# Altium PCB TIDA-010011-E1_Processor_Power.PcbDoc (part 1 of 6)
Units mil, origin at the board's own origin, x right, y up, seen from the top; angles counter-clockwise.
Board outline 4921.26 x 4921.26 mil, 4 copper layers (Top Layer, Gnd layer, Gnd/Pwr layer, Bottom Layer), stack 62.634 mil thick; 631 components, 254 nets, 1751 pads, 757 vias.
Unrouted connection lines stored in the file: 1.
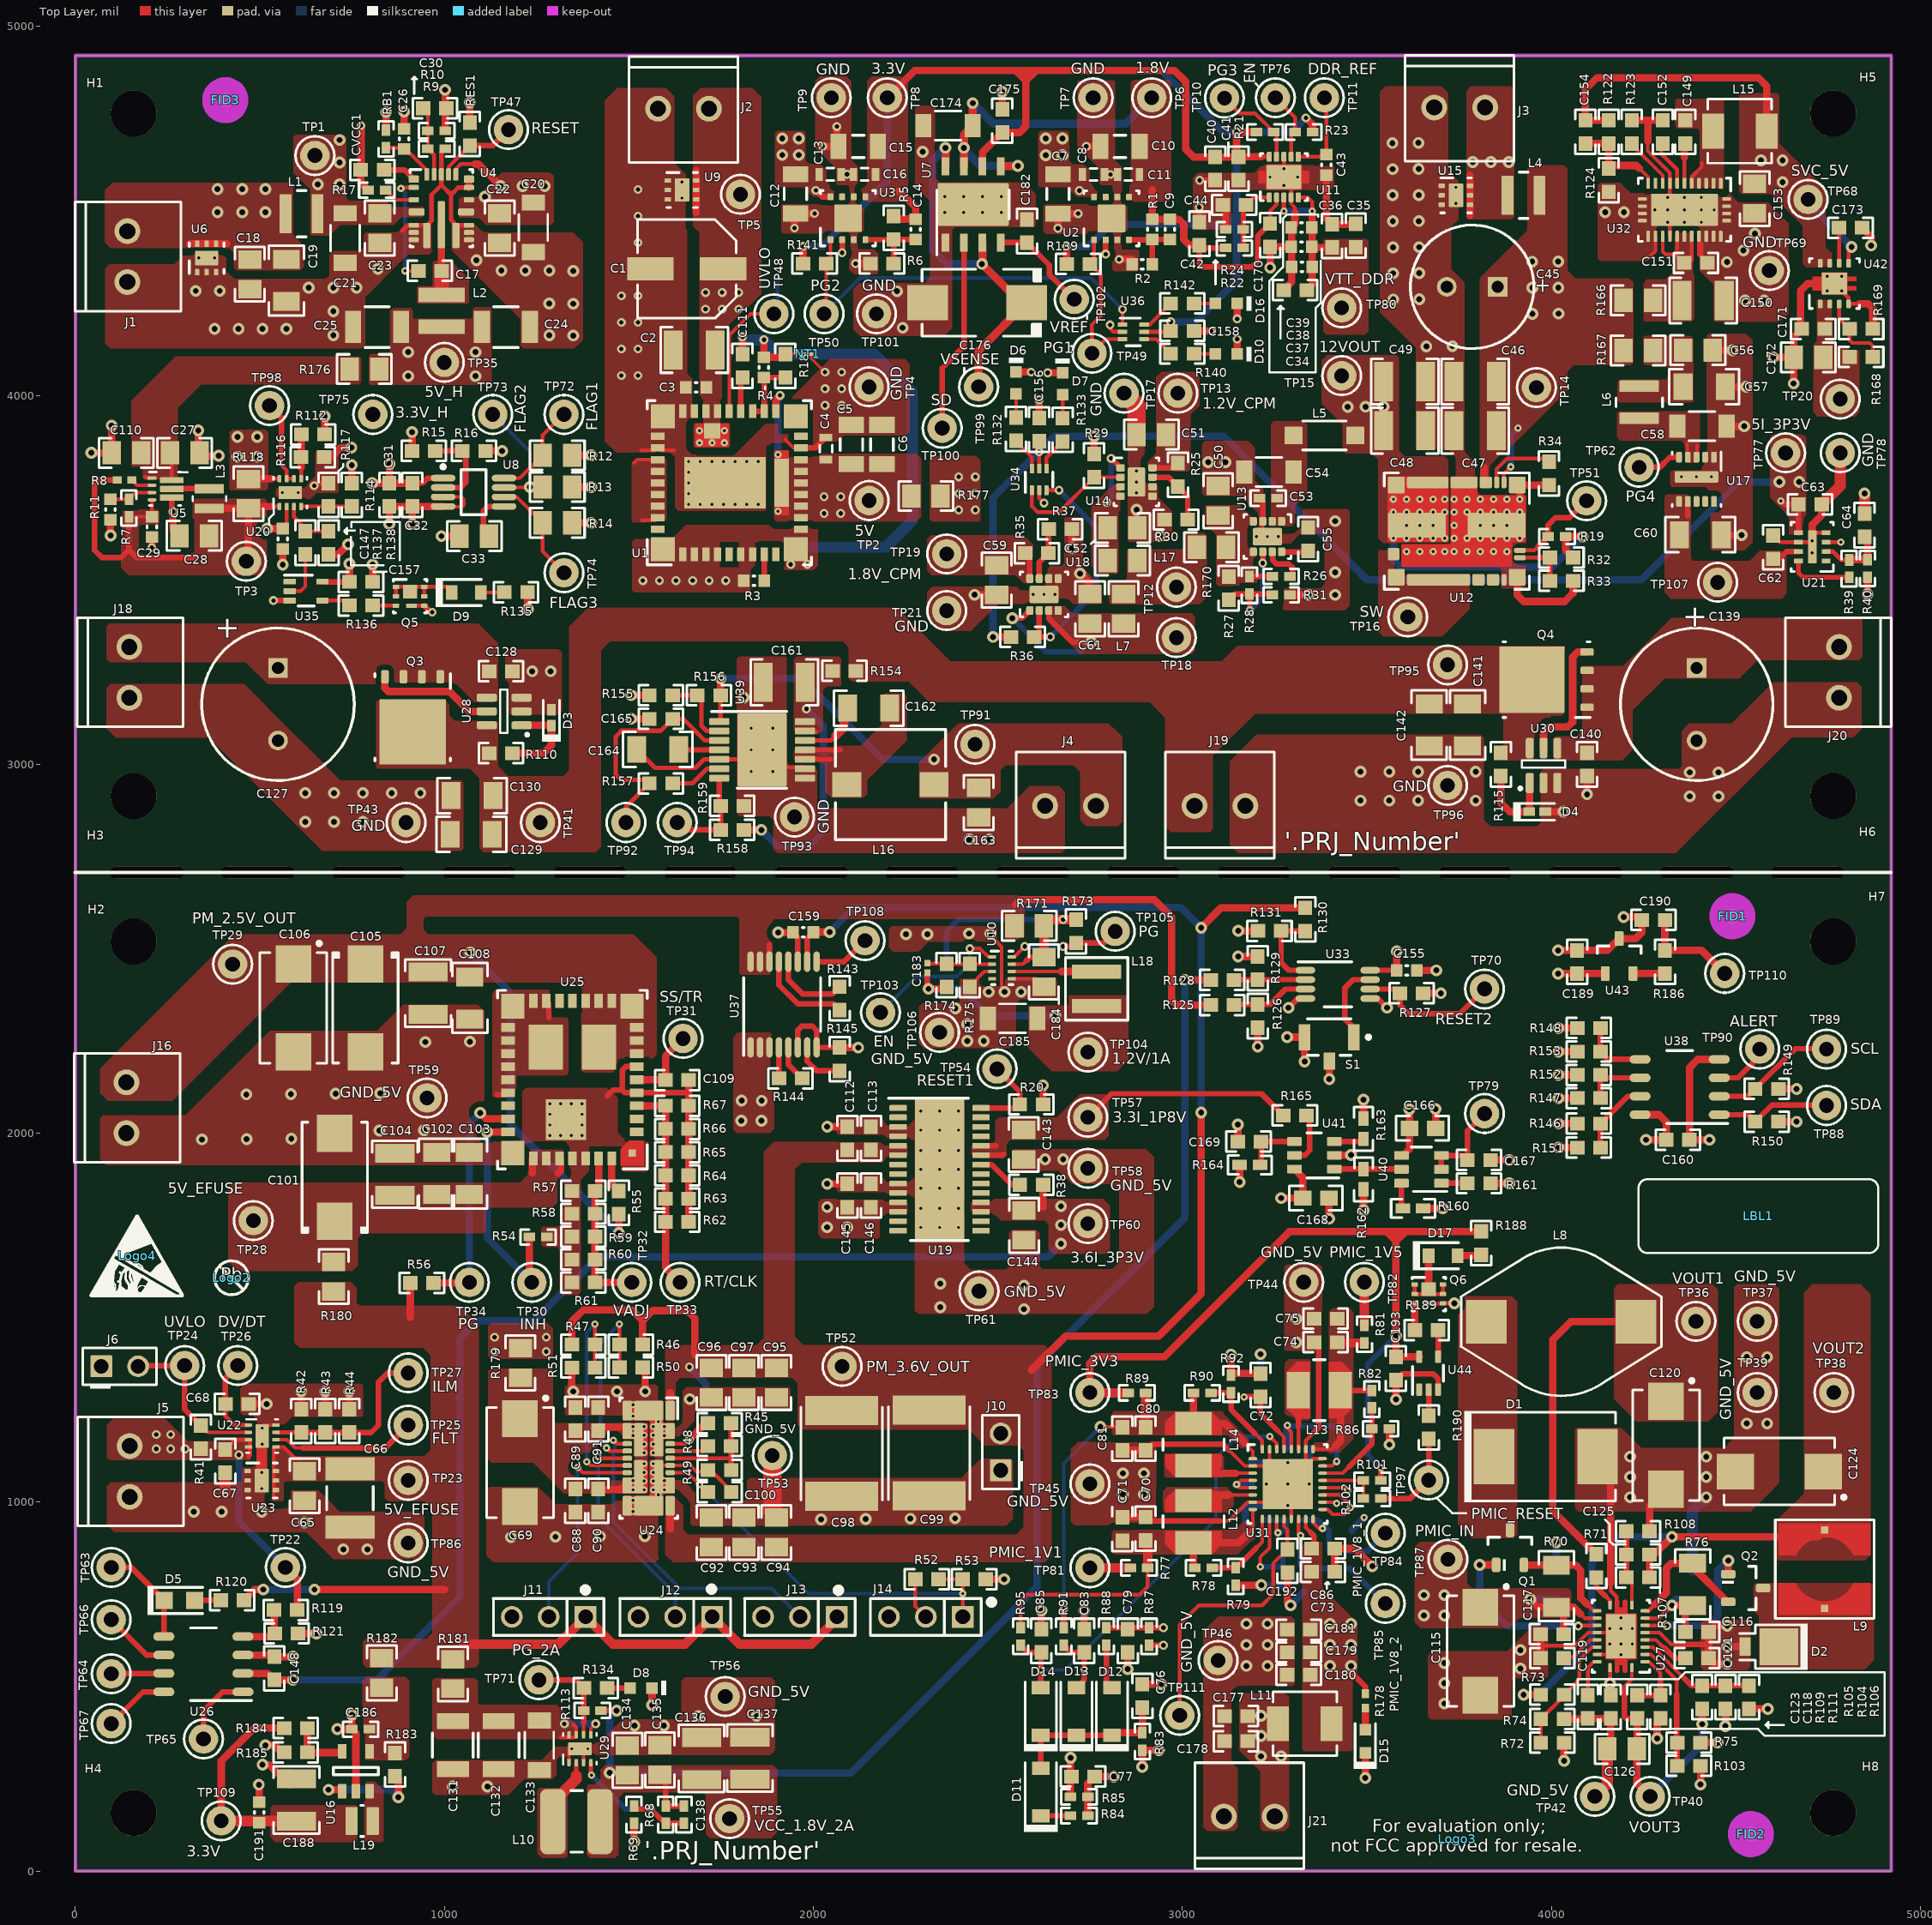
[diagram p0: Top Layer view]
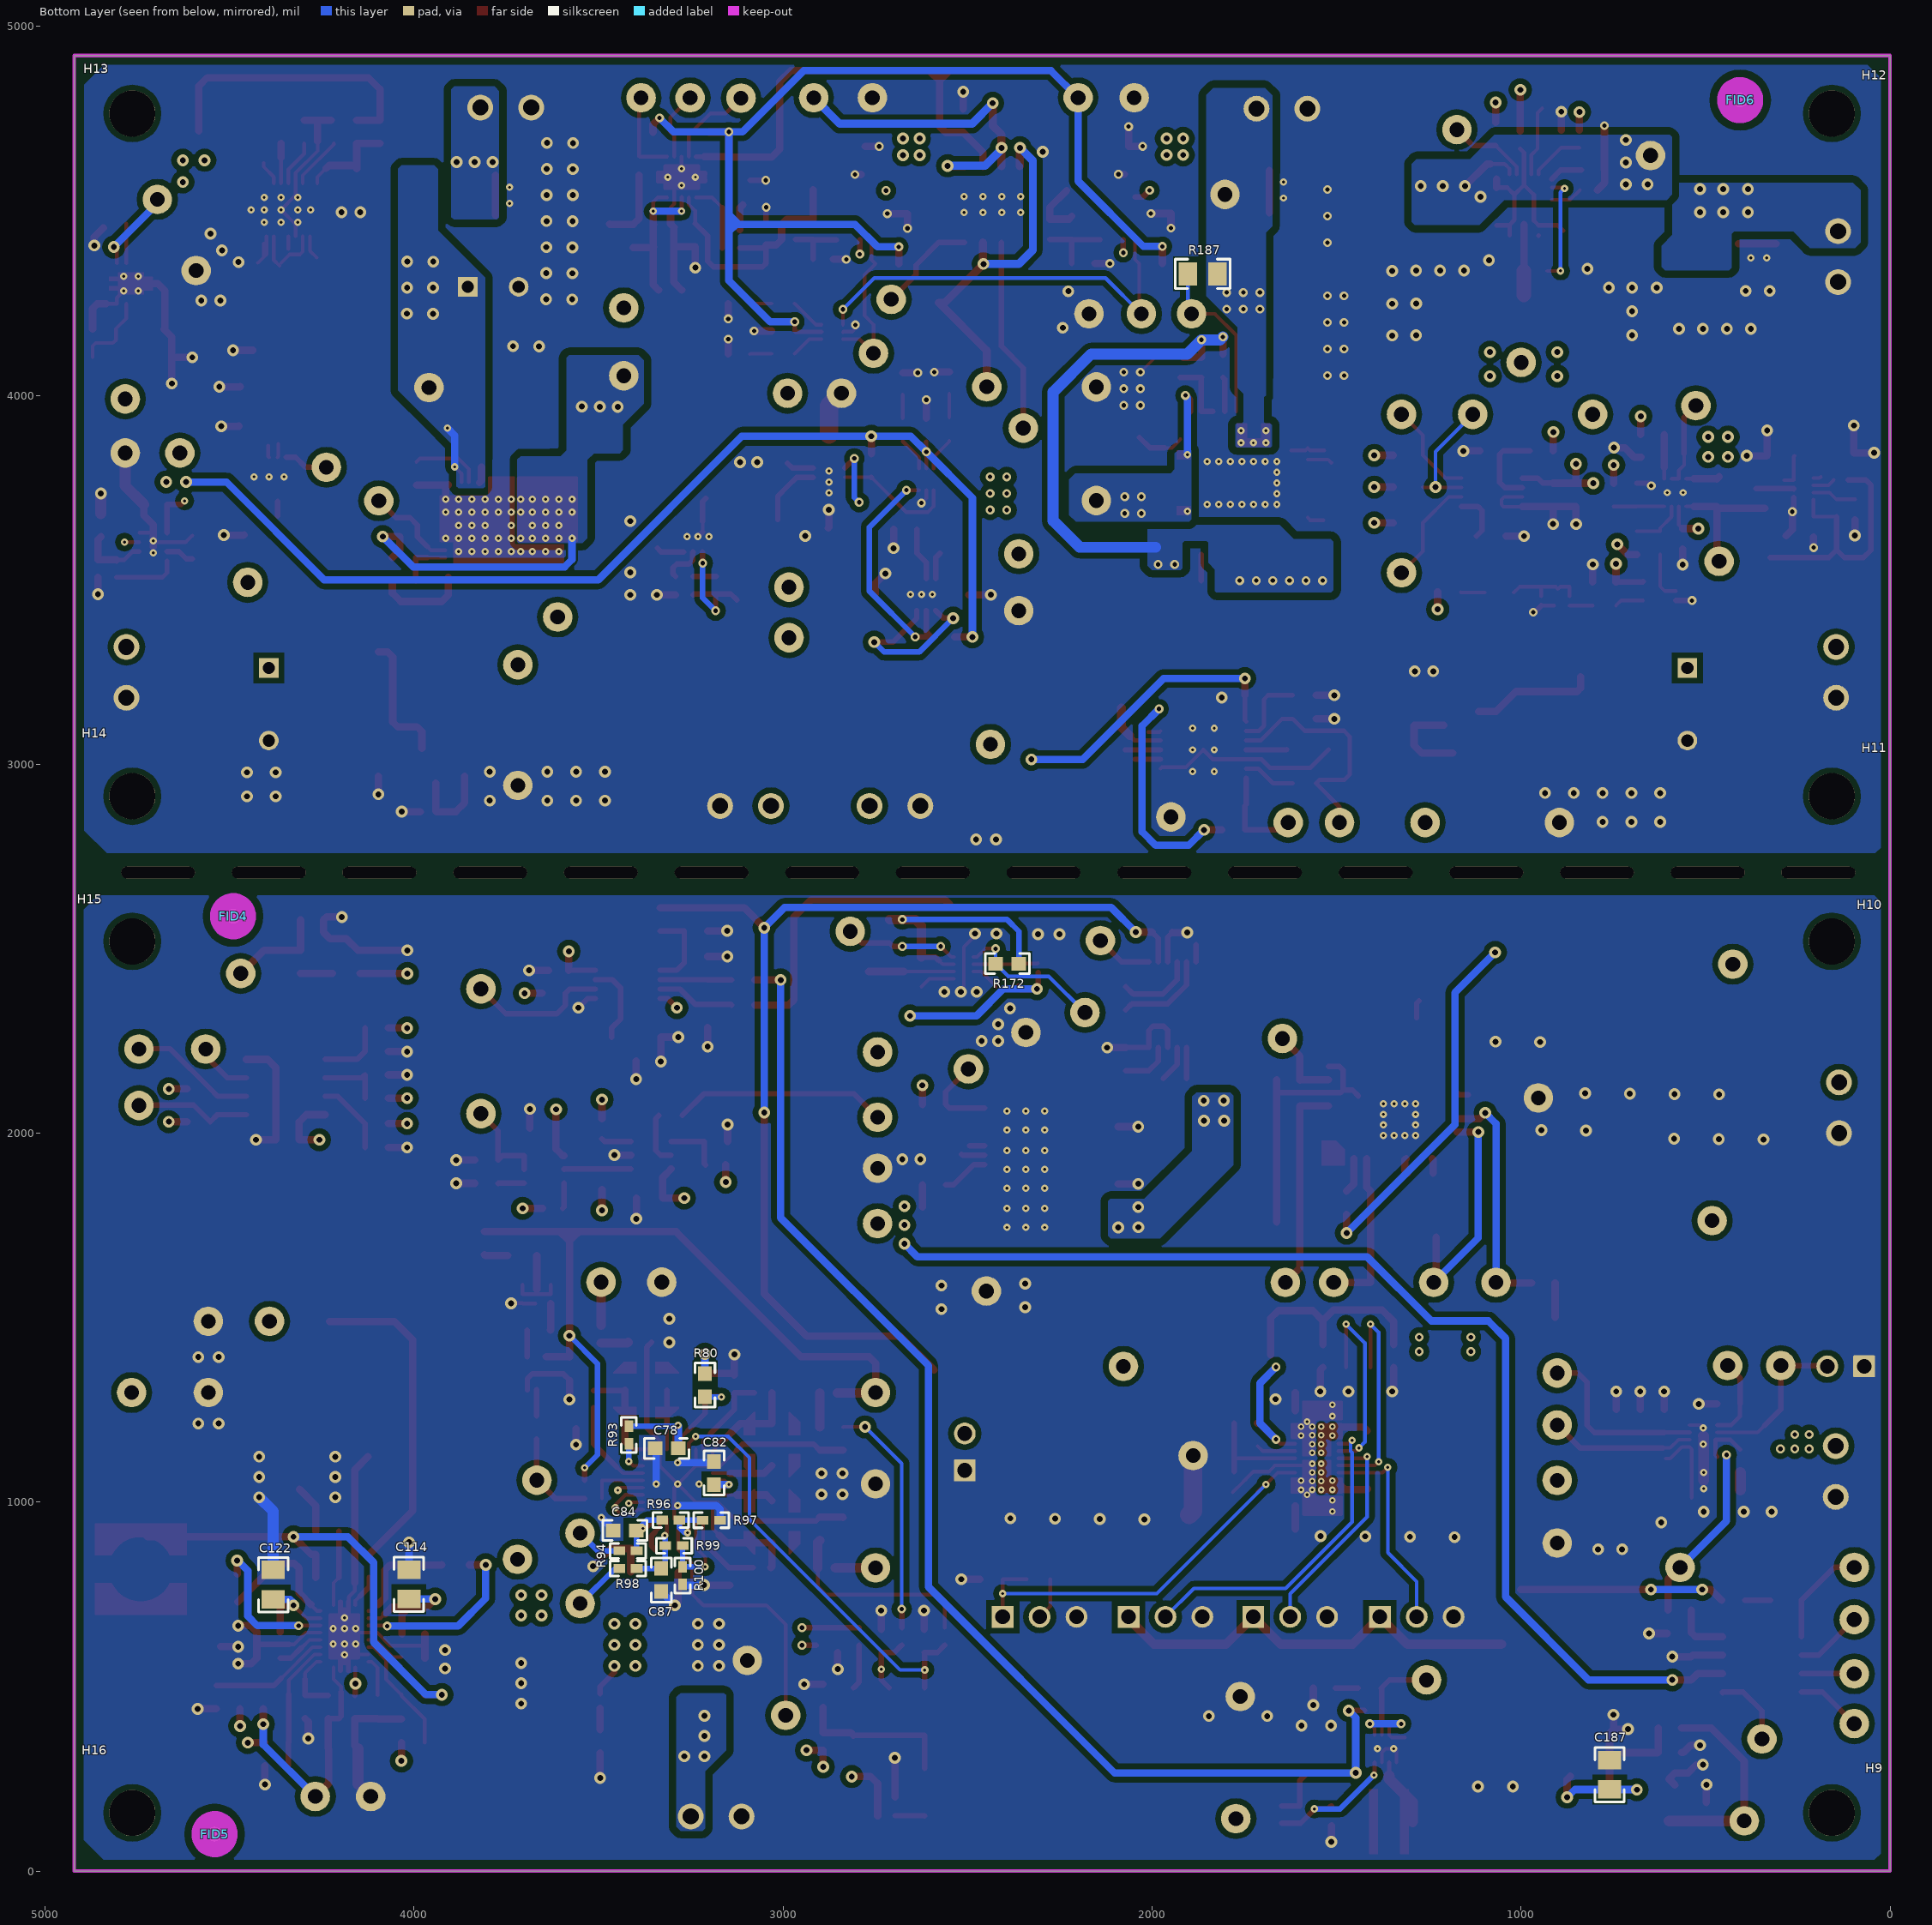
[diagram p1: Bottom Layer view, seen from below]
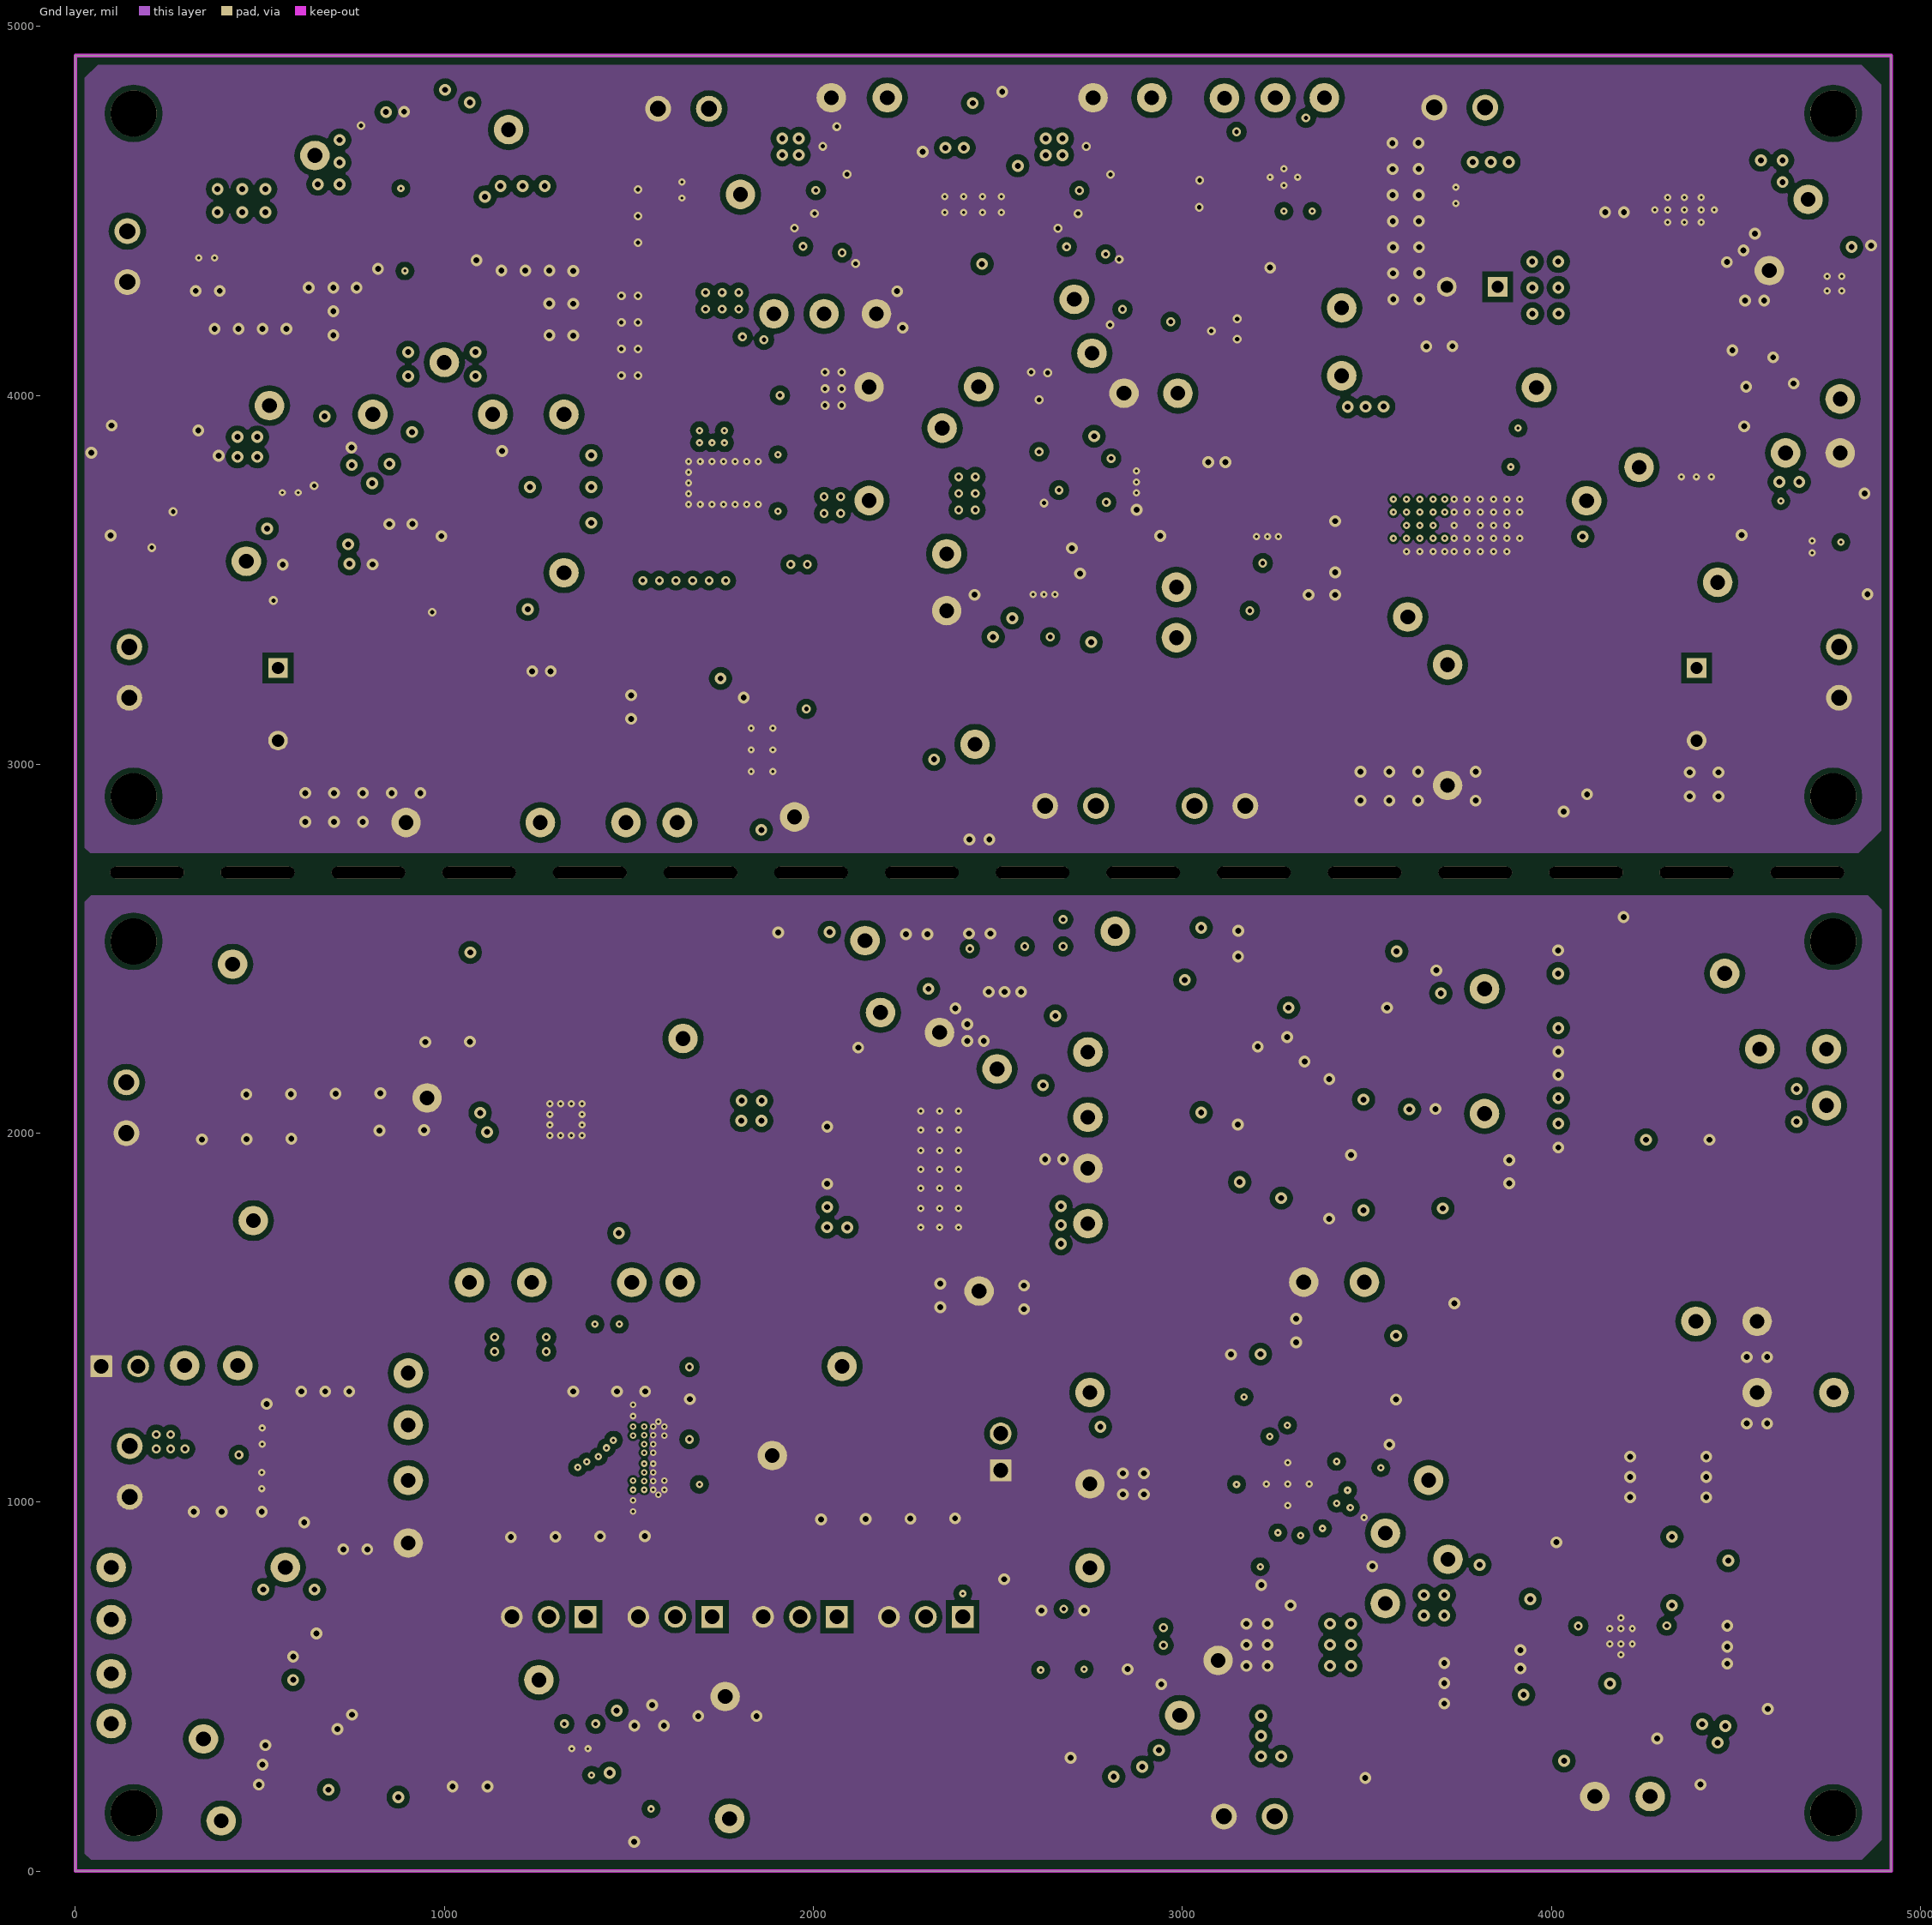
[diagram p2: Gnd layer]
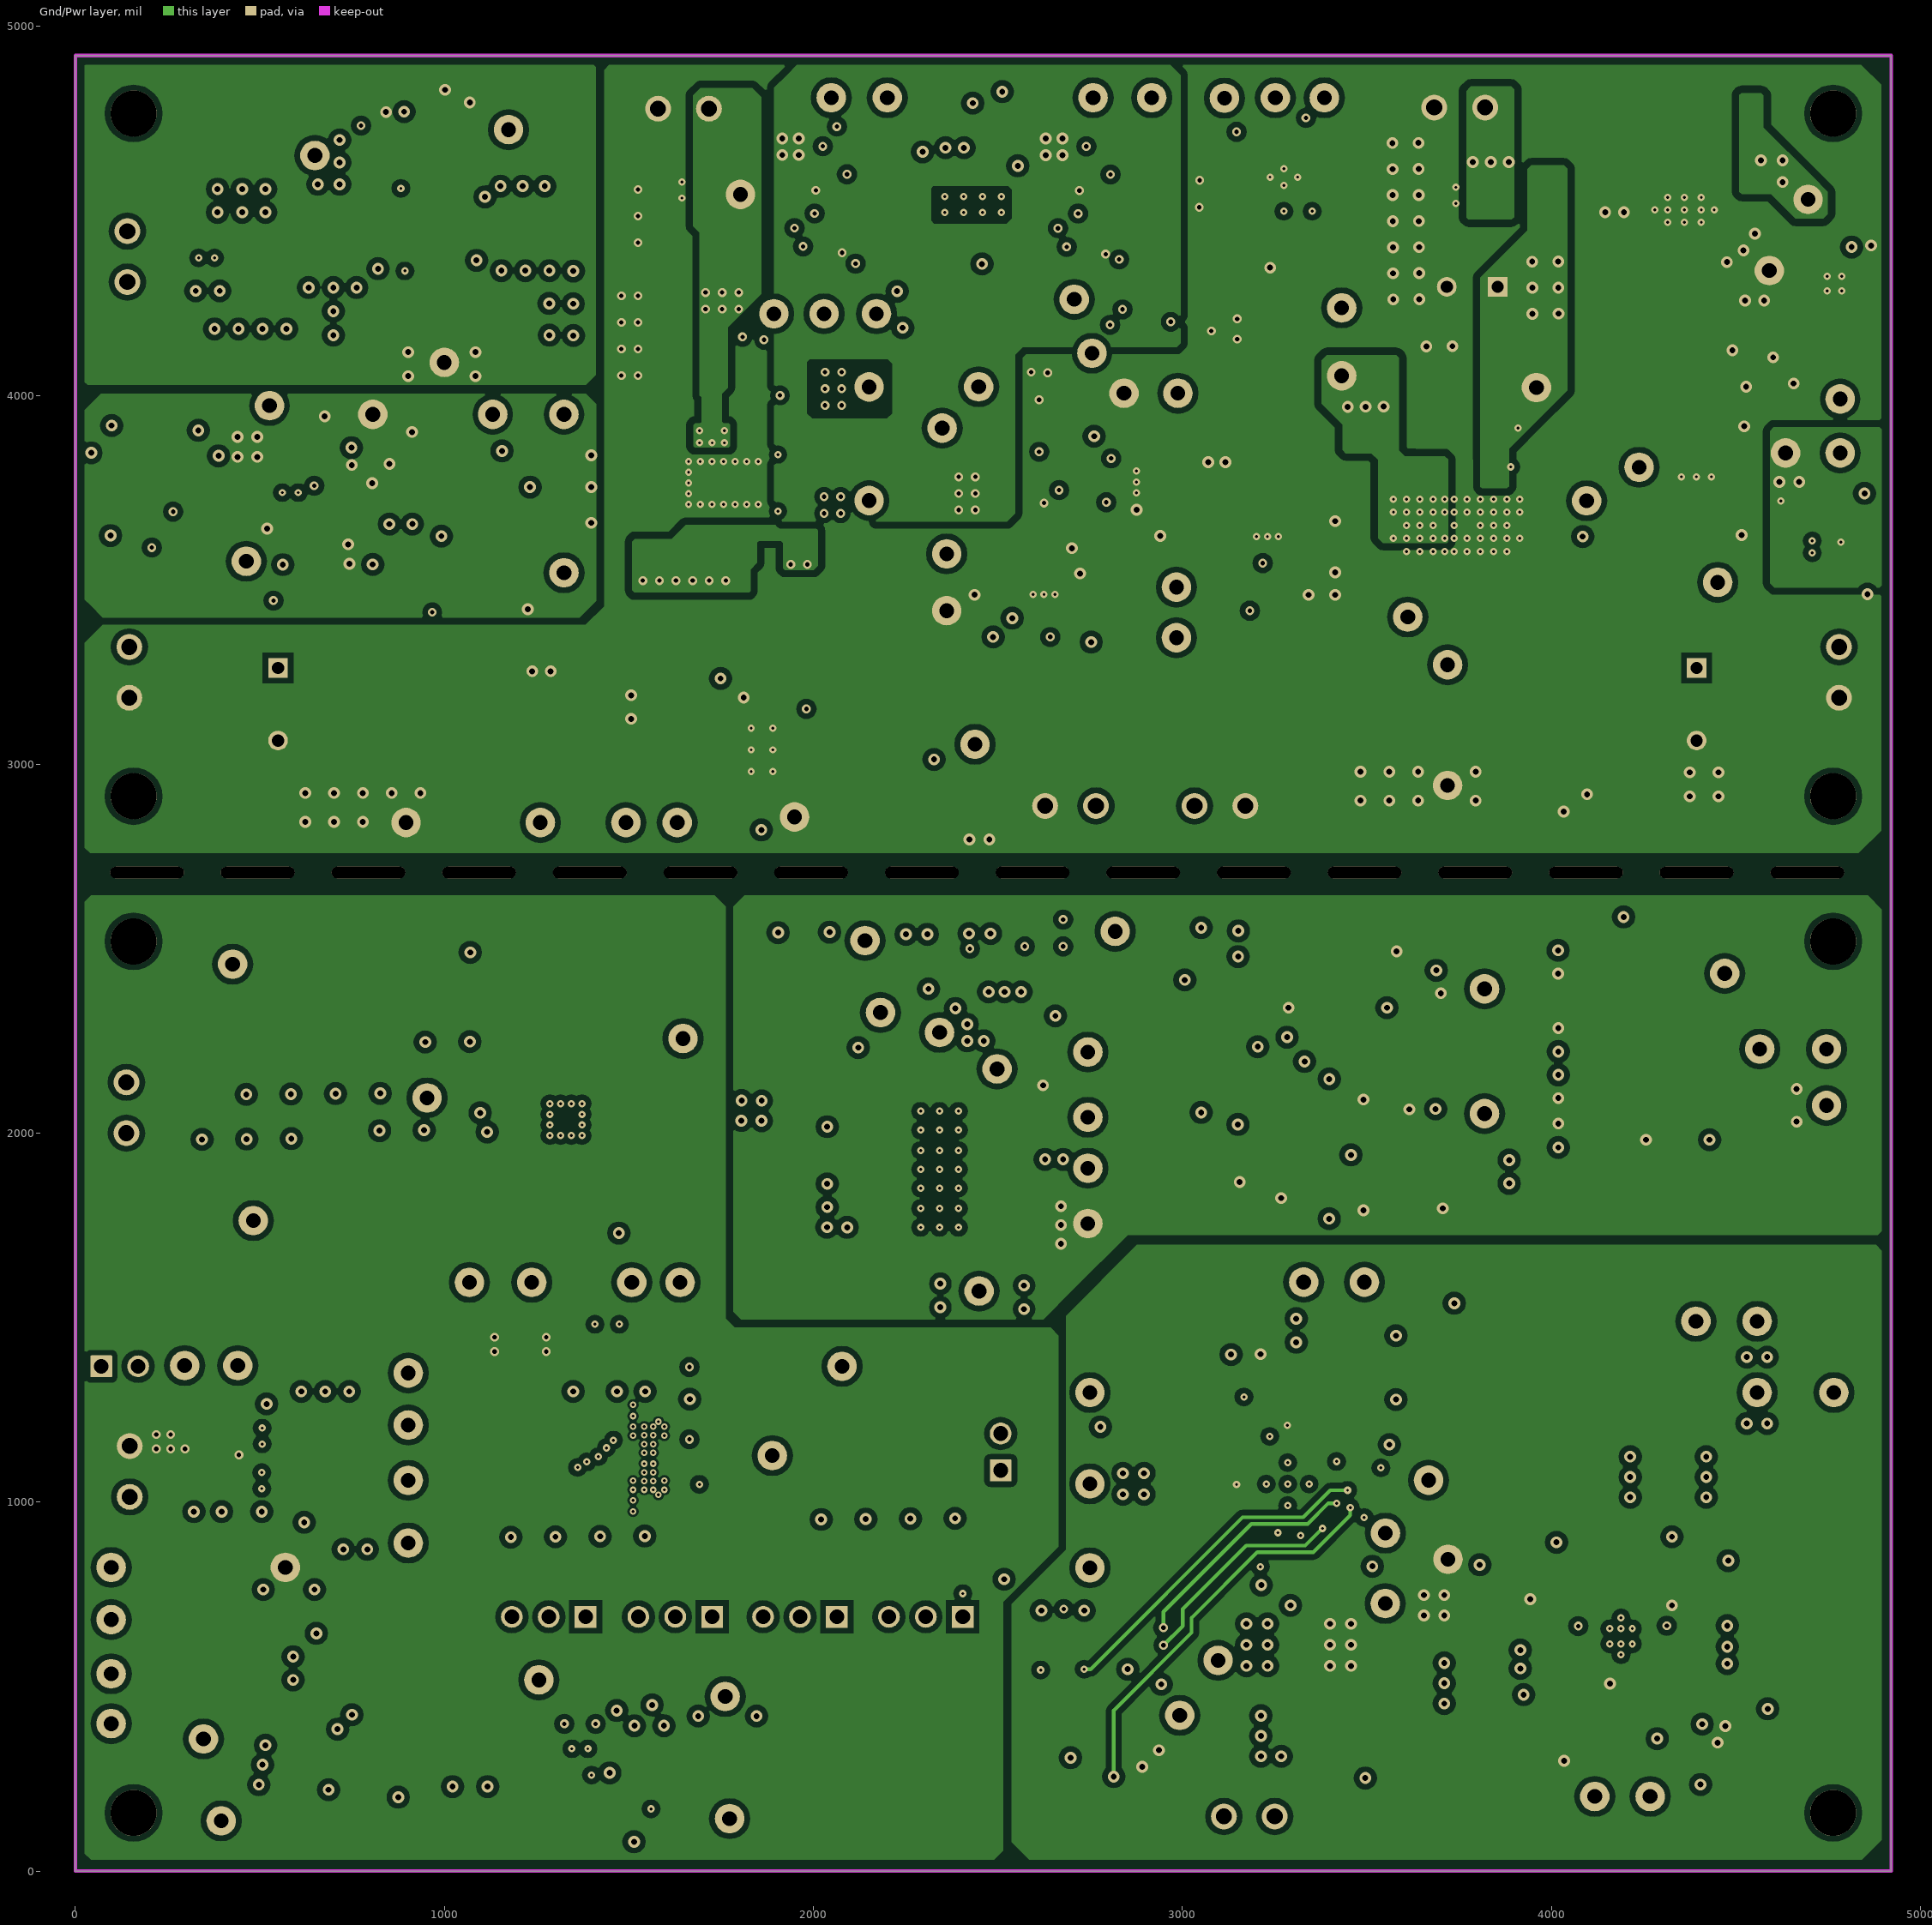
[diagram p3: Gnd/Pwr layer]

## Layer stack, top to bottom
Top Solder: solder mask 0.3, Solder Resist, Dk 3.5
Top Layer: signal copper 1.4
Dielectric1: core 16, FR-4 High Tg, Dk 4.2
Gnd layer: signal copper 1.417
Dielectric 2: prepreg 25, FR-4 High Tg, Dk 4.5
Gnd/Pwr layer: signal copper 1.417
Dielectric 3: core 16, FR-4 High Tg, Dk 4.2
Bottom Layer: signal copper 1.4
Bottom Solder: solder mask 0.3, Solder Resist, Dk 3.5

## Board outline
0,0 0,4921.26 4921.26,4921.26 4921.26,0

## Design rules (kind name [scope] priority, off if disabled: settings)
AcuteAngle [All] p1: minimum=4.50000000000000E+0001 checktracksonly=FALSE
AssemblyTestPointUsage [All] p1: valid=2
BoardOutlineClearance BoardOutlineClearance_MountingHoles [OnCopper and InComponentClass('Mounting Holes')] p1: gap=30 ignorepadtopadclearanceinfootprint=FALSE
BoardOutlineClearance BoardOutlineClearance_Poly [OnCopper and InPoly] p2: gap=25 ignorepadtopadclearanceinfootprint=FALSE
BoardOutlineClearance [OnCopper and Not InComponentClass('Logo') and not InComponentClass('FiducialMark') and not InRegion(1000,500,4000,800)] p3: gap=15 ignorepadtopadclearanceinfootprint=FALSE
Clearance Clearance_room_1 [WithinRoom('TIDA-010011-E1_Processor_Power _Pg8')] p1: gap=5.9 ignorepadtopadclearanceinfootprint=FALSE except(0: Arc-Hole Track-Hole SMDPad-Hole THPad-Hole Via-Hole Fill-Hole Poly-Hole Region-Hole Text-Hole)
Clearance Clearance_room1 [WithinRoom('RoomDefinition')] p2: gap=5.9 ignorepadtopadclearanceinfootprint=FALSE except(0: Arc-Hole Track-Hole SMDPad-Hole THPad-Hole Via-Hole Fill-Hole Poly-Hole Region-Hole Text-Hole)
Clearance Clearance_u4 [InPadClass('u4')] p3: gap=5.9 ignorepadtopadclearanceinfootprint=FALSE except(0: Arc-Hole Track-Hole SMDPad-Hole THPad-Hole Via-Hole Fill-Hole Poly-Hole Region-Hole Text-Hole)
Clearance Clearance_U11 [InPadClass('U11')] p4: gap=5.9 ignorepadtopadclearanceinfootprint=FALSE except(0: Arc-Hole Track-Hole SMDPad-Hole THPad-Hole Via-Hole Fill-Hole Poly-Hole Region-Hole Text-Hole)
Clearance Clearance_Poly_poly [InPoly vs InPoly] p5: gap=20 ignorepadtopadclearanceinfootprint=FALSE except(0: Arc-Hole Track-Hole SMDPad-Hole THPad-Hole Via-Hole Fill-Hole Poly-Hole Region-Hole Text-Hole)
Clearance Clearance_Keepouts [IsKeepOut vs InPolygon] p6: gap=20 ignorepadtopadclearanceinfootprint=FALSE except(0: Arc-Hole Track-Hole SMDPad-Hole THPad-Hole Via-Hole Fill-Hole Poly-Hole Region-Hole Text-Hole)
Clearance Clearance_Poly [InPolygon] p7: gap=15 ignorepadtopadclearanceinfootprint=FALSE except(0: Arc-Hole Track-Hole SMDPad-Hole THPad-Hole Via-Hole Fill-Hole Poly-Hole Region-Hole Text-Hole)
Clearance [All] p8: gap=7.7 ignorepadtopadclearanceinfootprint=FALSE except(0: Arc-Hole Track-Hole SMDPad-Hole THPad-Hole Via-Hole Fill-Hole Poly-Hole Region-Hole Text-Hole)
ComponentClearance ComponentClearance_MountingHoles_FiducialMarks [InComponentClass('Mounting Holes') vs InComponentClass('FiducialMark')] p1: gap=10 collisioncheckmode=3 verticalgap=10 showdistances=FALSE
ComponentClearance ComponentClearance_Shunt [InComponentClass('Header') vs InComponentClass('Shunt')] p2: gap=0 collisioncheckmode=3 verticalgap=0 showdistances=FALSE
ComponentClearance ComponentClearance_Logo [InComponentClass('Logo')] p3: gap=5 collisioncheckmode=3 verticalgap=5 showdistances=FALSE
ComponentClearance ComponentClearance_ScrewToNut [(HasFootprint('NY PMS 440 0025 PH')) vs (HasFootprint('Keystone_1902C'))] p4: gap=5 collisioncheckmode=3 verticalgap=10 showdistances=FALSE
ComponentClearance ComponentClearance_MountingHoles [InComponentClass('Mounting Holes')] p5: gap=250 collisioncheckmode=3 verticalgap=100000 showdistances=FALSE
ComponentClearance ComponentClearance_SmallPassives [HasFootprint('0201*') or HasFootprint('0402*') or HasFootprint('0508') or HasFootprint('0603*') or HasFootprint('0612') or HasFootprint('0805*') or HasFootprint('0815*') or HasFootprint('0830*') or HasFootprint('1206*') or HasFootprint('1210*') or HasFootprint('1808*') or HasFootprint('1812*') or HasFootprint('1825*') or HasFootprint('2010*') or HasFootprint('2220*') or HasFootprint('2225*') or HasFootprint('2512*') or HasFootprint('2728*') or HasFootprint('3518*') vs HasFootprint('0201*') or HasFootprint('0402*') or HasFootprint('0508') or HasFootprint('0603*') or HasFootprint('0612') or HasFootprint('0805*') or HasFootprint('0815*') or HasFootprint('0830*') or HasFootprint('1206*') or HasFootprint('1210*') or HasFootprint('1808*') or HasFootprint('1812*') or HasFootprint('1825*') or HasFootprint('2010*') or HasFootprint('2220*') or HasFootprint('2225*') or HasFootprint('2512*') or HasFootprint('2728*') or HasFootprint('3518*')] p6: gap=5 collisioncheckmode=3 verticalgap=5 showdistances=FALSE
ComponentClearance ComponentClearance_THtoSMT [IsThruComponent vs IsSMTComponent] p7: gap=5 collisioncheckmode=3 verticalgap=5 showdistances=FALSE
ComponentClearance ComponentClearance_THtoTH [IsThruComponent vs IsThruComponent] p8: gap=0 collisioncheckmode=3 verticalgap=10 showdistances=FALSE
ComponentClearance [All] p9: gap=10 collisioncheckmode=3 verticalgap=10 showdistances=FALSE
DiffPairsRouting [All] p1: maxlimit=100 minlimit=10 mostfreqgap=10 toplayer_minwidth=15 toplayer_maxwidth=15 toplayer_prefwidth=15 midlayer1_minwidth=15 midlayer1_maxwidth=15 midlayer1_prefwidth=15 midlayer2_minwidth=15 midlayer2_maxwidth=15 midlayer2_prefwidth=15 bottomlayer_minwidth=15 bottomlayer_maxwidth=15 bottomlayer_prefwidth=15 maxuncoupledlength=1000
FabricationTestPointUsage TestPointUsage [All] p1: valid=2 allowmultiple=FALSE
FabricationTestpoint Testpoint [All] p1: side=3 testpointundercomponent=TRUE minsize=40 maxsize=100 preferedsize=60 minholesize=0 maxholesize=40 preferedholesize=32 testpointgrid=1 allowsidetop=TRUE allowsidebottom=TRUE usegrid=TRUE gridtolerance=0.01
FanoutControl Fanout_LCC [IsLCC] p1: bgadir=Out bgaviamode=Centered fanoutstyle=Auto fanoutdirection=Alternating viagrid=1 // Fanout_LCC (Default Rule)
FanoutControl Fanout_BGA [IsBGA] p2: bgadir=Out bgaviamode=Centered fanoutstyle=Auto fanoutdirection=Alternating viagrid=1 // Fanout_BGA (Default Rule)
FanoutControl Fanout_Default [All] p4: bgadir=Out bgaviamode=Centered fanoutstyle=Auto fanoutdirection=Alternating viagrid=1 // Fanout_Default (Default Rule)
FanoutControl Fanout_Small [(CompPinCount < 5)] p5: bgadir=Out bgaviamode=Centered fanoutstyle=Auto fanoutdirection=OutThenIn viagrid=1 // Fanout_Small (Default Rule)
Height [All] p1: minheight=0 maxheight=99999 prefheight=500
HoleSize [All] p1: absolutevalues=TRUE maxlimit=251 minlimit=7.87 maxpercent=80.000 minpercent=20.000
MinimumAnnularRing [All] p1: minimumring=4
MinimumSolderMaskSliver MinimumSolderMaskSliver_Logo [InComponentClass('Logo') vs InComponentClass('Logo')] p1: minsoldermaskwidth=0.7
MinimumSolderMaskSliver [All] p2: minsoldermaskwidth=3.94
PlaneClearance [All] p1: clearance=10
PlaneConnect [All] p1: planeconnectstyle=Relief reliefexpansion=10 reliefentries=4 reliefconductorwidth=10 reliefairgap=10
PolygonConnect PolygonConnectThermalVia [isvia] p1: connectstyle=Direct reliefconductorwidth=10 reliefentries=4 polygonreliefangle="90 Angle" airgapwidth=10
PolygonConnect PolygonConnectThermalPad [((ObjectKind = 'Pad') And (((Name Like 'U*') or (Name Like 'D*')) and (InComponentClass('TIDA-00183_pg-4_Driver') or InComponentClass('TIDA-00183_pg-5_OP_Connector')))) or ((ObjectKind = 'Pad') And (Name like 'U61*'))] p2: connectstyle=Direct reliefconductorwidth=10 reliefentries=4 polygonreliefangle="90 Angle" airgapwidth=10
PolygonConnect [All] p3: connectstyle=Direct reliefconductorwidth=10 reliefentries=4 polygonreliefangle="90 Angle" airgapwidth=5
RoomDefinition "TIDA-010011-E1_Processor_Power _Pg8" [InComponentClass('TIDA-010011-E1_Processor_Power _Pg8')] p1: confinementstyle=ConfineOut formatcopy=TRUE lockcomponents=FALSE outline 1474.99,1282.31 1632.47,1282.31 1632.47,955.54 1474.99,955.54
RoomDefinition [u12] p2: confinementstyle=ConfineOut formatcopy=TRUE lockcomponents=FALSE outline 3546.85,3789.57 3940.56,3789.57 3940.56,3474.61 3546.85,3474.61
RoutingVias ThermalPadVias [IsVia and InAnyComponent] p1: holewidth=7.87 width=19.68 viastyle="Through Hole" minholewidth=7.87 minwidth=17.72 maxholewidth=12.99 maxwidth=23.62
RoutingVias [All] p2: holewidth=12 width=24 viastyle="Through Hole" minholewidth=8 minwidth=20 maxholewidth=16 maxwidth=32
SilkToBoardRegionClearance [Not ((IsComment or IsDesignator) And (Hide <> 'False')) and not InRegion(1000,500,4000,800)] p1:
SilkToSilkClearance SilkToSilkClearance_Pb-FreeLogo [(HasFootprint('Pb-Free_Overlay_Medium') OR HasFootprint('Pb-Free_Overlay_Small')) vs (HasFootprint('Pb-Free_Overlay_Medium') OR HasFootprint('Pb-Free_Overlay_Small'))] p1: silktosilkclearance=0
SilkToSilkClearance [All] p2: silktosilkclearance=4
SilkToSolderMaskClearance SilkToComponentPadClearance [IsPad and InAnycomponent] p1: minsilkscreentomaskgap=5 clearancetoexposedcopper=TRUE
SilkToSolderMaskClearance "Silk to Solder Mask Opening" [All] p2: minsilkscreentomaskgap=4 clearancetoexposedcopper=FALSE
SolderMaskExpansion [All] p1: expansion=1.97
Width [All] p1: maxlimit=100 minlimit=6 preferedwidth=10 checkconnectedcopper=TRUE
13 further rules are at their usual default settings.

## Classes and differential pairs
component class "TIDA-010011-E1_Processor_Power _Pg9": C131 C132 C133 C134 C135 C136 C137 C138 C183 C184 C185 C186 C187 C188 C191 D8 L10 L18 L19 R68 R69 R113 R134 R171 R172 R173 R174 R175 R181 R182 R183 R184 R185 TP55 TP56 TP71 TP103 TP104 TP105 TP106 TP109 U10 U16 U29
pad class U11: U8-1 U8-2 U8-3 U8-4 U8-5 U8-6 U8-7 U8-8 U11-1 U11-2 U11-3 U11-4 U11-5 U11-6 U11-7 U11-8 U11-9 U11-10 U11-11 U12- U12-1 U12-2 U12-3 U12-4 U12-5 U12-6 U12-7 U12-8 U12-9 U12-10 U12-11 U12-12 U12-13 U12-14 U12-15 U12-16 U12-17 U12-18 U13-0 U13-1 U13-2 U13-3 U13-4 U13-5 U13-6 U13-7 U13-8 U13-9 U14-1 U14-2 U14-3 U14-4 U14-5 U14-6 U14-7 U14-8 U14-9 U18-1 U18-2 U18-3 U18-4 U18-5 U18-6 U18-7 U18-8 U18-9 U24-1 U24-2 U24-3 U24-4 U24-5 U24-6 U24-7 U24-8 U24-9 U24-10 U24-11 U24-12 U24-13 U24-14 U24-15 U24-16 U24-17 U24-18 U24-19 U24-20 U24-21 U24-22 U24-23 U24-24
component class "TIDA-010011-E1_Processor_Power _Pg3": C17 C18 C19 C20 C21 C22 C23 C24 C25 C26 C27 C28 C29 C30 C31 C32 C33 C110 C147 C157 CVCC1 D9 J1 L1 L2 L3 Q5 R7 R8 R9 R10 R11 R12 R13 R14 R15 R16 R17 R112 R114 R116 R117 R118 R135 R136 R137 R138 R176 RB1 RES1 TP1 TP3 TP35 TP47 TP72 TP73 TP74 TP75 TP98 U4 U5 U6 U8 U20 U35
component class "TIDA-010011-E1_Processor_Power _Pg4": C1 C2 C3 C4 C5 C6 C7 C8 C9 C10 C11 C12 C13 C14 C15 C16 C34 C35 C36 C37 C38 C39 C40 C41 C42 C43 C44 C111 C158 C170 C174 C175 C176 C182 D10 D16 J2 NT1 R1 R2 R3 R4 R5 R6 R18 R21 R22 R23 R24 R139 R140 R141 R142 R177 R187 TP2 TP4 TP5 TP6 TP7 TP8 TP9 TP10 TP11 TP48 TP49 TP50 TP76 TP80 TP99 TP100 TP101 TP102 U1 U2 U3 U7 U9 U11 U36
component class "TIDA-010011-E1_Processor_Power _EVM_Hardware_Pg11": FID1 FID2 FID3 FID4 FID5 FID6 H1 H2 H3 H4 H5 H6 H7 H8 H9 H10 H11 H12 H13 H14 H15 H16 LBL1 Logo2 Logo3 Logo4 ZZ1 ZZ2 ZZ3 ZZ4
component class FiducialMark: FID1 FID2 FID3 FID4 FID5 FID6
component class AssemblyNote: ZZ1 ZZ2 ZZ3 ZZ4
component class Header: J6 J10 J11 J12 J13 J14
component class "TIDA-010011-E1_Processor_Power _Pg5": C45 C46 C47 C48 C49 C50 C51 C52 C53 C54 C55 C56 C57 C58 C59 C60 C61 C62 C63 C64 C156 D6 D7 J3 L4 L5 L6 L7 L17 R19 R25 R26 R27 R28 R29 R30 R31 R32 R33 R34 R35 R36 R37 R39 R40 R132 R133 R167 R170 TP12 TP13 TP14 TP15 TP16 TP17 TP18 TP19 TP21 TP51 TP62 TP77 TP78 TP107 U12 U13 U14 U15 U17 U18 U21 U34
component class "TIDA-010011-E1_Processor_Power _Pg7": C65 C66 C67 C68 C69 C88 C89 C90 C91 C92 C93 C94 C95 C96 C97 C98 C99 C100 C148 D5 J5 J6 J10 J11 J12 J13 J14 R41 R42 R43 R44 R45 R46 R47 R48 R49 R50 R51 R52 R53 R119 R120 R121 R179 TP22 TP23 TP24 TP25 TP26 TP27 TP52 TP53 TP63 TP64 TP65 TP66 TP67 TP86 U22 U23 U24 U26
component class "TIDA-010011-E1_Processor_Power _Pg8": C101 C102 C103 C104 C105 C106 C107 C108 C109 C112 C113 C143 C144 C145 C146 C155 C159 C166 C167 C168 C169 J16 R20 R38 R54 R55 R56 R57 R58 R59 R60 R61 R62 R63 R64 R65 R66 R67 R125 R126 R127 R128 R129 R130 R131 R143 R144 R145 R160 R161 R162 R163 R164 R165 R180 S1 TP28 TP29 TP30 TP31 TP32 TP33 TP34 TP54 TP57 TP58 TP59 TP60 TP61 TP70 TP79 TP108 U19 U25 U33 U37 U40 U41
component class "TIDA-010011-E1_Processor_Power _Pg10": C114 C115 C116 C117 C118 C119 C120 C121 C122 C123 C124 C125 C126 C160 C189 C190 D1 D2 L8 L9 Q1 Q2 R70 R71 R72 R73 R74 R75 R76 R103 R104 R105 R106 R107 R108 R109 R111 R146 R147 R148 R149 R150 R151 R152 R153 R186 TP36 TP37 TP38 TP39 TP40 TP42 TP87 TP88 TP89 TP90 TP110 U27 U38 U43
component class "TIDA-010011-E1_Processor_Power _Pg11": C70 C71 C72 C73 C74 C75 C76 C77 C78 C79 C80 C81 C82 C83 C84 C85 C86 C87 C177 C178 C179 C180 C181 C192 C193 D11 D12 D13 D14 D15 D17 J21 L11 L12 L13 L14 Q6 R77 R78 R79 R80 R81 R82 R83 R84 R85 R86 R87 R88 R89 R90 R91 R92 R93 R94 R95 R96 R97 R98 R99 R100 R101 R102 R178 R188 R189 R190 TP44 TP45 TP46 TP81 TP82 TP83 TP84 TP85 TP97 TP111 U31 U44
component class "TIDA-010011-E1_Processor_Power _Pg6": C127 C128 C129 C130 C139 C140 C141 C142 C149 C150 C151 C152 C153 C154 C161 C162 C163 C164 C165 C171 C172 C173 D3 D4 J4 J18 J19 J20 L15 L16 Q3 Q4 R110 R115 R122 R123 R124 R154 R155 R156 R157 R158 R159 R166 R168 R169 TP20 TP41 TP43 TP68 TP69 TP91 TP92 TP93 TP94 TP95 TP96 U28 U30 U32 U39 U42
pad class u4: U4-1 U4-2 U4-3 U4-4 U4-4A U4-4B U4-5 U4-6 U4-7 U4-8 U4-8A U4-8B U4-9 U4-9A U4-9B U4-9C U4-9D U4-10 U4-10A U4-10B U4-11 U4-12 U4-13 U4-14 U4-14A U4-14B U4-15 U4-16 U4-17 U4-18 U4-19 U4-20 U4-21 U4-22 U5-1 U5-2 U5-3 U5-4 U5-5 U5-6 U5-7
component class Label: LBL1

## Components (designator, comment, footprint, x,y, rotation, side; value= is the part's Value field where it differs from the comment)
C1 "EEE-FK1H470XP" SM_RADIAL_D8 1657.01,4342.77 r180 top value=47uF
C2 "GRM32ER71H106KA12L" 1210 1677.01,4122.77 r180 top value=10uF
C3 "GRM188R71H104KA93D" 0603L 1682.01,4021.77 r0 top value=0.1uF
C4 "GRM188R71A225KE15D" 0603S 2034.01,3855.77 r90 top value=2.2uF
C5 "GRM31CR61A476KE15L" 1206L 2103.01,3866.77 r90 top value=47uF
C6 "GRM31CR61A476KE15L" 1206L 2186.01,3866.77 r90 top value=47uF
C7 "GRM31CR61A476KE15L" 1206L 2663.07,4545.57 r270 top value=47uF
C8 "GRM188R71A225KE15D" 0603S 2759.07,4598.57 r0 top value=2.2uF
C9 "GRM1885C1H160JA01D" 0603L 2966.07,4449.83 r270 top value=16pF
C10 "GRM31CR71A226KE15L" 1206L 2831.07,4674.57 r180 top value=22uF
C11 "GRM188R71A225KE15D" 0603S 2854.07,4598.57 r180 top value=2.2uF
C12 "GRM31CR61A476KE15L" 1206L 1951.5,4545.99 r270 top value=47uF
C13 "GRM188R71A225KE15D" 0603S 2045.5,4598.99 r0 top value=2.2uF
C14 "GRM1885C1H200JA01D" 0603L 2277.5,4449.99 r270 top value=20pF
C15 "GRM31CR71A226KE15L" 1206L 2121.5,4674.56 r180 top value=22uF
C16 "GRM188R71A225KE15D" 0603S 2138.5,4598.99 r180 top value=2.2uF
C17 "GCM188R71E474KA64D" 0603#1 960.74,4337.1 r0 top value=0.47uF
C18 "C2012X7R2A104K125AA" 0805_HV 472.74,4328.1 r270 top value=0.1uF
C19 "C3216X7R1V475K085AC" 1206 571.74,4311.1 r270 top value=4.7uF
C20 "GRM31CR71E106KA12L" 1206_180 1240.74,4455.1 r270 top value=10uF
C21 "GRM31CR71E106KA12L" 1206_180 730.74,4426.1 r270 top value=10uF
C22 "C2012X7R2A104K125AA" 0805_HV 1149.74,4453.1 r270 top value=0.1uF
C23 "C2012X7R2A104K125AA" 0805_HV 824.74,4453.1 r270 top value=0.1uF
C24 "CGA6P1X7R1C226M250AC" 1210_280 1166.74,4185.1 r0 top value=22uF
C25 "CGA6P1X7R1C226M250AC" 1210_280 817.74,4185.1 r180 top value=22uF
C26 "GRM188R71H104KA93D" 0603L 890.74,4695.1 r90 top value=0.1uF
C27 "JMK212BJ226KG-T" 0805_HV 296,3844 r0 top value=22uF
C28 "JMK212BJ226KG-T" 0805_HV 322,3619 r180 top value=22uF
C29 "GRM188R71H104KA93D" 0603L 207,3643.26 r270 top value=0.1uF
C30 "06035A101JAT2A" 0603#1 974,4778 r0 top value=100pF
C31 "CL10B105KQ8NNNC" 0603#1 851,3730.26 r270 top value=1uF
C32 "0603ZC104KAT2A" 0603#1 913,3730.26 r270 top value=0.1uF
C33 "08055C473KAT2A" 0805_HV 1081,3618.26 r180 top value=0.047uF
C34 "C1608X5R1E106M080AC" 0603#1 3306,4285 r180 top value=10uF
C35 "C1608X5R1E106M080AC" 0603#1 3470,4433 r90 top value=10uF
C36 "C1608X5R1E106M080AC" 0603#1 3406,4432 r90 top value=10uF
C37 "GRM188R71H104KA93D" 0603L 3324.2,4347.8 r180 top value=0.1uF
C38 "GRM188R71H104KA93D" 0603L 3323.2,4402.8 r180 top value=0.1uF
C39 "GRM188R71H104KA93D" 0603L 3323.2,4454.8 r180 top value=0.1uF
C40 "C1608X5R1E106M080AC" 0603#1 3089.12,4614.46 r270 top value=10uF
C41 "C1608X5R1E106M080AC" 0603#1 3152.12,4614.46 r270 top value=10uF
C42 "GRM188R61C475KAAJ" 0603#1 3046,4438 r90 top value=4.7uF
C43 "GRM188R71H104KA93D" 0603L 3390.12,4624.46 r270 top value=0.1uF
C44 "C0603C102K3GACTU" 0603#1 3141,4516 r180 top value=1000pF
C45 "EKZN101ELL470MH15D" KZN_800x1500 3785.71,4294.09 r180 top value=47uF
C46 "GRM32ER71H475KA88L" 1210_270 3793.71,4037.09 r180 top value=4.7uF
C47 "GRM32ER71H475KA88L" 1210_270 3793.71,3904.09 r180 top value=4.7uF
C48 "GRM32ER71E226KE15L" 1210_270 3602.71,3904.09 r0 top value=22uF
C49 "GRM32ER71E226KE15L" 1210_270 3602.71,4037.09 r0 top value=22uF
C50 "JMK212BJ226MG-T" 0805_HV 3097,3714 r90 top value=22uF
C51 "JMK212BJ226KG-T" 0805_HV 2916,3893.5 r180 top value=22uF
C52 "GRM21BR71A106KE51L" 0805_HV 2838,3640.5 r0 top value=10uF
C53 "GRM1555C1H471JA01D" 0402#1 3232.74,3721 r180 top value=470pF
C54 "C3216X7R1E106M160AE" 1206_190 3234.67,3792 r180 top value=10uF
C55 "GRM1885C1H332JA01D" 0603#1 3341,3610 r270 top value=3300pF
C56 "C2012X7R2A104K125AA" 0805_HV 4397.38,4122.26 r0 top value=0.1uF
C57 "C3216X7R1V475K085AC" 1206 4414.38,4023.26 r0 top value=4.7uF
C58 "CL31B106KBHNNNE" 1206_180 4408.38,3916.26 r0 top value=10uF
C59 "JMK212BJ226KG-T" 0805_HV 2496.74,3499.24 r270 top value=22uF
C60 "C3216X5R1C476M160AB" 1206 4404,3622 r0 top value=47uF
C61 "GRM21BR71A106KE51L" 0805_HV 2749.74,3421.24 r90 top value=10uF
C62 "C1608X5R1E106M080AC" 0603#1 4601.4,3588.2 r90 top value=10uF
C63 "C1608X5R1E106M080AC" 0603#1 4701.4,3704.2 r0 top value=10uF
C64 "GRM188R71H471KA01D" 0603#1 4849,3648 r90 top value=470pF
C65 "08053D105KAT2A" 0805_HV 621,1044 r270 top value=1uF
C66 "C4532X5R1E226M250KA" 1812_280 744,1011 r270 top value=22uF
C67 "GRM188R71E104KA01D" 0603#1 406,1111 r270 top value=0.1uF
C68 "GRM188R71E103KA01D" 0603#1 438,1266 r0 top value=0.01uF
C69 "293D107X9020E2TE3" 7343-43 1204.73,1106.92 r270 top value=100uF
C70 "C1608X5R1E106M080AC" 0603#1 2900.49,927.84 r90 top value=10uF
C71 "C1608X5R1E106M080AC" 0603#1 2837.49,926.84 r90 top value=10uF
C72 "C1608X7R1C105K080AC" 0603#1 3212,1317 r270 top value=1uF
C73 "C1608X5R1E106M080AC" 0603#1 3381.5,811 r0 top value=10uF
C74 "C1608X5R1E106M080AC" 0603#1 3388.49,1433.11 r180 top value=10uF
C75 "C1608X5R1E106M080AC" 0603#1 3388.49,1497.11 r180 top value=10uF
C76 "C1608X7R1C105K080AC" 0603#1 2891.53,474.62 r90 top value=1uF
C77 "C1608X7R1C105K080AC" 0603#1 2731,256 r180 top value=1uF
C78 "C1608X5R1E106M080AC" 0603#1 3315.49,1145.84 r0 bottom value=10uF
C79 "C1608X7R1C105K080AC" 0603#1 2852,624 r270 top value=1uF
C80 "C1608X5R1E106M080AC" 0603#1 2900.42,1171.84 r270 top value=10uF
C81 "C1608X5R1E106M080AC" 0603#1 2837.42,1171.84 r270 top value=10uF
C82 "C1608X5R1E106M080AC" 0603#1 3187.49,1078.84 r90 bottom value=10uF
C83 "C1608X7R1C105K080AC" 0603#1 2734,624 r90 top value=1uF
C84 "GRM188R71A225KE15D" 0603#1 3429,923 r0 bottom value=2.2uF
C85 "C1608X7R1C105K080AC" 0603#1 2618,624 r90 top value=1uF
C86 "C1608X7R1C105K080AC" 0603#1 3381.5,874.02 r0 top value=1uF
C87 "GRM188R71A225KE15D" 0603#1 3330.49,788.84 r270 bottom value=2.2uF
C88 "GRM188R61A226ME15D" 0603#1 1354.67,1003.92 r270 top value=22uF
C89 "GRM188R61A226ME15D" 0603#1 1354.73,1224.92 r90 top value=22uF
C90 "GRM188R61A226ME15D" 0603#1 1416.67,1003.92 r270 top value=22uF
C91 "GRM188R61A226ME15D" 0603#1 1416.73,1224.92 r90 top value=22uF
C92 "GRM21BR61E226ME44L" 0805_HV 1723.73,917.92 r90 top value=22uF
C93 "GRM21BR61E226ME44L" 0805_HV 1811.73,917.92 r90 top value=22uF
C94 "GRM21BR61E226ME44L" 0805_HV 1899.73,917.92 r90 top value=22uF
C95 "GRM21BR61E226ME44L" 0805_HV 1899.73,1323.92 r270 top value=22uF
C96 "GRM21BR61E226ME44L" 0805_HV 1723.73,1323.92 r270 top value=22uF
C97 "GRM21BR61E226ME44L" 0805_HV 1811.73,1323.92 r270 top value=22uF
C98 "CKG57NX7S1E476M500JH" CKG57N 2076.73,1131.92 r270 top value=47uF
C99 "CKG57NX7S1E476M500JH" CKG57N 2313.73,1132.92 r270 top value=47uF
C100 "GRM188R71H332KA01D" 0603#1 1746,1027 r180 top value=3300pF
C101 "10TPE220ML" 7343-30 702.72,1880.51 r90 top value=220uF
C102 "C1206C104J5RACTU" 1206 978.72,1890.51 r90 top value=0.1uF
C103 "C1206C104J5RACTU" 1206 1067.72,1890.51 r90 top value=0.1uF
C104 "GRM32ER61A476KE20L" 1210_270 865.72,1888.51 r90 top value=47uF
C105 "10TPE220ML" 7343-30 785.72,2339.51 r270 top value=220uF
C106 "6TPE100MI" 7343-20 590.72,2339.51 r270 top value=100uF
C107 "GRM32ER60J476ME20L" 1210_270 955.72,2379.51 r270 top value=47uF
C108 "C1206C104J5RACTU" 1206 1068.72,2366.51 r270 top value=0.1uF
C109 "GRM188R71E103KA01D" 0603#1 1630.72,2144.05 r180 top value=0.01uF
C110 "JMK212BJ226KG-T" 0805_HV 138,3844 r180 top value=22uF
C111 "C0603C223K4RACTU" 0603#1 1808.01,4079.77 r90 top value=0.022uF
C112 "UMK107AB7105KA-T" 0603#1 2092,1986 r90 top value=1uF
C113 "UMK107AB7105KA-T" 0603#1 2156,1986 r90 top value=1uF
C114 "CGA4J1X7S1C106K125AC" 0805_HV 4014,777 r90 bottom value=10uF
C115 "6TPE100MI" 7343-20 3808,596 r270 top value=100uF
C116 "C0603C104Z4VACTU" 0603#1 4395,648 r0 top value=0.1uF
C117 "C0603C104Z4VACTU" 0603#1 4002,642 r180 top value=0.1uF
C118 "GRM185C80J105KE26D" 0603#1 4161,445 r270 top value=1uF
C119 "GRM188R71H152KA01D" 0603#1 4002.5,577 r180 top value=1500pF
C120 "6TPE100MI" 7343-20 4311,1154 r270 top value=100uF
C121 "GRM188R71H152KA01D" 0603#1 4395,577 r0 top value=1500pF
C122 "CGA4J1X7S1C106K125AC" 0805_HV 4382,776 r90 bottom value=10uF
C123 "GRM188R71E103KA01D" 0603#1 4099,445 r270 top value=0.01uF
C124 "6TPE100MI" 7343-20 4618,1083 r180 top value=100uF
C125 "C0603C100F5GAC7867" 0603#1 4235,858 r180 top value=10pF
C126 "GRM21BR71A106KE51L" 0805_HV 4192,331 r180 top value=10uF
C127 "EKZE250ELL681MJ20S" Chemi-Con_1000x2000 549,3162.57 r270 top value=680uF
C128 "GRM188R61H105KAALD" 0603#1 1153,3252 r0 top value=1uF
C129 "C3216X7R1H105K" 1206 1073,2810 r180 top value=1uF
C130 "C1206C104J5RACTU" 1206 1075,2915 r180 top value=0.1uF
C131 "C3225X7R1C226K250AC" 1210_280 1023,341 r270 top value=22uF
C132 "C3225X7R1C226K250AC" 1210_280 1147,341 r270 top value=22uF
C133 "C3216X7R1E106M160AE" 1206_190 1257,341 r270 top value=10uF
C134 "C2012X7S1A226M125AC" 0805_HV 1496,300 r90 top value=22uF
C135 "C2012X7S1A226M125AC" 0805_HV 1584,301 r90 top value=22uF
C136 "GRM32ER71A476KE15L" 1210_270 1697,305 r90 top value=47uF
C137 "GRM32ER71A476KE15L" 1210_270 1828,306 r90 top value=47uF
C138 "GCM1555C1H220JA16D" 0402#1 1649,153 r270 top value=22pF
C139 "EKZE250ELL681MJ20S" Chemi-Con_1000x2000 4394,3162.57 r270 top value=680uF
C140 "GRM188R61H105KAALD" 0603#1 4097,2999.43 r270 top value=1uF
C141 "C3216X7R1H105K" 1206 3773,3106.43 r270 top value=1uF
C142 "C1206C104J5RACTU" 1206 3669,3106.43 r270 top value=0.1uF
C143 "C2012X5R1A336M125AC" 0805_HV 2570,1969 r270 top value=33uF
C144 "C2012X5R1A336M125AC" 0805_HV 2571,1750 r270 top value=33uF
C145 "UMK107AB7105KA-T" 0603#1 2092,1831 r90 top value=1uF
C146 "UMK107AB7105KA-T" 0603#1 2156,1831 r90 top value=1uF
C147 "GRM188R71H104KA93D" 0603L 562,3611 r270 top value=0.1uF
C148 "GRM188R71E104KA01D" 0603#1 538.81,549.48 r90 top value=0.1uF
C149 "C1608X7R1H474K080AC" 0603#1 4363,4714 r90 top value=0.47uF
C150 "GRM32ER71H106KA12L" 1210_270 4411.74,4257 r0 top value=10uF
C151 "C1608X7R1H474K080AC" 0603#1 4391.74,4359 r0 top value=0.47uF
C152 "C0603C225M8PACTU" 0603#1 4302,4714 r270 top value=2.2uF
C153 "GRM21BR61A476ME15" 0805_HV 4551,4533 r270 top value=47uF
C154 "CGA3E2C0G1H470J080AA" 0603#1 4092.74,4714 r270 top value=47pF
C155 "GRM188R71H104KA93D" 0603L 3608.3,2441.31 r180 top value=0.1uF
C156 "06033D104KAT2A" 0603#1 2612,3907 r90 top value=0.1uF
C157 "GMK107BJ104KAHT" 0603#1 774,3494.26 r0 top value=0.1uF
C158 "06033D104KAT2A" 0603#1 3000,4174.46 r0 top value=0.1uF
C159 "GRM188R71H104KA93D" 0603L 1972.47,2544.78 r180 top value=0.1uF
C160 "06033C104KAT2A" 0603#1 4343,1982 r180 top value=0.1uF
C161 "GRM32ER71H106KA12L" 1210 1921,3222 r180 top value=10uF
C162 "C1206C104J5RACTU" 1206 2150,3152 r0 top value=0.1uF
C163 "GRM21BR61E226ME44L" 0805_HV 2448,2896 r270 top value=22uF
C164 "C1206C104J5RACTU" 1206 1578,3040 r0 top value=0.1uF
C165 "GRM185C80J105KE26D" 0603#1 1587,3123 r0 top value=1uF
C166 "06033C104JAT2A" 0603M 3651,2013 r0 top value=0.1uF
C167 "UMK107AB7105KA-T" 0603#1 3804,1927 r0 top value=1uF
C168 "06033C104JAT2A" 0603M 3362,1824 r180 top value=0.1uF
C169 "06035A151JAT2A" 0603#2 3179.42,1977 r180 top value=150pF
C170 "C1608X5R1E106M080AC" 0603#1 3238,4434 r270 top value=10uF
C171 "C1608X5R1E106M080AC" 0603#1 4709.94,4179.8 r180 top value=10uF
C172 "C2012X7R2A104K125AA" 0805_HV 4696.94,4102.8 r180 top value=0.1uF
C173 "0603ZC103KAT2A" 0603#1 4811,4454 r0 top value=0.01uF
C174 "GRM31CR71A226KE15L" 1206_180 2365,4731 r0 top value=22uF
C175 "06033D104KAT2A" 0603#1 2512,4744 r90 top value=0.1uF
C176 "EEF-GX0D331R" GX_2TERM 2444,4251 r180 top value=330uF
C177 "GRM188R61C475KAAJ" 0603#1 3145.49,419.84 r180 top value=4.7uF
C178 "GRM188R71C104KA01D" 0603#1 3145.49,351.84 r180 top value=0.1uF
C179 "GRM188R61A226ME15D" 0603#1 3315.49,592.84 r180 top value=22uF
C180 "GRM188R61A226ME15D" 0603#1 3315.49,531.84 r180 top value=22uF
C181 "GRM188R71C104KA01D" 0603#1 3315.49,654.16 r180 top value=0.1uF
C182 "06033D104KAT2A" 0603#1 2579,4445 r90 top value=0.1uF
C183 "GRM033R71E121KA01D" 0201 2309,2448 r90 top value=120pF
C184 "C2012X7R1V475K125AC" 0805_HV 2625,2437 r270 top value=4.7uF
C185 "EMK316BB7226ML-T" 1206_190 2540,2311 r180 top value=22uF
C186 "GRM155R60J475ME47D" 0402#1 772.97,384.53 r180 top value=4.7uF
C187 "08053D105KAT2A" 0805_HV 759.97,261 r90 bottom value=1uF
C188 "GRM32ER71H106KA12L" 1210 598.97,192.53 r90 top value=10uF
C189 "06033C104KAT2A" 0603#1 4070,2464 r270 top value=0.1uF
C190 "06033C104KAT2A" 0603#1 4277,2578 r0 top value=0.1uF
C191 "GRM188R71H104KA93D" 0603L 497.61,158.58 r270 top value=0.1uF
C192 "GRM188R71A225KE15D" 0603#1 3285,840.5 r270 top value=2.2uF
C193 "GMK107BJ104KAHT" 0603#1 3579,1362 r270 top value=0.1uF
CVCC1 "CGB3B1X5R1A475K055AC" 0603#1 804.74,4611.1 r180 top value=4.7uF
D1 "SS32-E3/57T" SMC 3985,1123 r0 top value=20V
D2 "MBRM120ET1G" POWERMITE 4571,608 r180 top value=20V
D3 "BZT52C4V7T-7" SOD-523 1290,3126 r90 top value=4.7V
D4 "BZT52C4V7T-7" SOD-523 3962,2871.43 r0 top value=4.7V
D5 "CMP-0002829-2" LED_LTST-C170_Red 281.81,733.48 r180 top value=Red
D6 "LTST-C190KGKT" LED_LTST-C190_G 2549.54,4033.41 r90 top value=Green
D7 "LTST-C190KGKT" LED_LTST-C190_G 2675.54,4031.41 r90 top value=Green
D8 "LTST-C190KGKT" LED_LTST-C190_G 1533,496 r0 top value=Green
D9 "LG M67K-G1J2-24-Z" LG_M67K_Green 1059,3465.26 r0 top value=Green
D10 "LTST-C190KGKT" LED_LTST-C190_G 3119,4111.72 r0 top value=Green
D11 "MBR0540T1G" SOD-123 2616.21,214 r90 top value=40V
D12 "MBR0540T1G" SOD-123 2809,432 r90 top value=40V
D13 "MBR0540T1G" SOD-123 2713.11,432.21 r90 top value=40V
D14 "MBR0540T1G" SOD-123 2616,432 r90 top value=40V
D15 "150060VS75000" WL-SMCW_GREEN 3496,352 r90 top value=Green
D16 "LTST-C190KGKT" LED_LTST-C190_G 3119,4249.17 r0 top value=Green
D17 "LG M67K-G1J2-24-Z" LG_M67K_Green 3707,1668 r0 top value=Green
FID1 "Fiducial" Fiducial10-30 4491,2588 r0 top
FID2 "Fiducial" Fiducial10-30 4541,100 r90 top
FID3 "Fiducial" Fiducial10-30 406,4800 r90 top
FID4 "Fiducial" Fiducial10-30 4491,2588 r90 bottom
FID5 "Fiducial" Fiducial10-30 4541,100 r90 bottom
FID6 "Fiducial" Fiducial10-30 406,4800 r90 bottom
H1 "NSP-4-3-01" B_F_PMSSS4400025PH 157.48,4763.78 r0 top
H2 "NSP-4-3-01" B_F_PMSSS4400025PH 157.48,2519.69 r0 top
H3 "NSP-4-3-01" B_F_PMSSS4400025PH 157.48,2913.39 r0 top
H4 "NSP-4-3-01" B_F_PMSSS4400025PH 157.48,157.48 r0 top
H5 "NSP-4-3-01" B_F_PMSSS4400025PH 4763.78,4763.78 r0 top
H6 "NSP-4-3-01" B_F_PMSSS4400025PH 4763.78,2913.39 r0 top
H7 "NSP-4-3-01" B_F_PMSSS4400025PH 4763.78,2519.69 r0 top
H8 "NSP-4-3-01" B_F_PMSSS4400025PH 4763.78,157.48 r0 top
H9 "1902E" Keystone_1902E 157.48,157.48 r180 bottom
H10 "1902E" Keystone_1902E 157.48,2519.69 r180 bottom
H11 "1902E" Keystone_1902E 157.48,2913.39 r180 bottom
H12 "1902E" Keystone_1902E 157.48,4763.78 r180 bottom
H13 "1902E" Keystone_1902E 4763.78,4763.78 r180 bottom
H14 "1902E" Keystone_1902E 4763.78,2913.39 r180 bottom
H15 "1902E" Keystone_1902E 4763.78,2519.69 r180 bottom
H16 "1902E" Keystone_1902E 4763.78,157.48 r180 bottom
J1 "1751248" CONN_1751248 140.74,4376 r270 top
J2 "1751248" CONN_1751248 1648.01,4776.77 r180 top
J3 "1751248" CONN_1751248 3751.71,4780.09 r180 top
J4 "1751248" CONN_1751248 2697,2887 r0 top
J5 "1751248" CONN_1751248 147,1083 r270 top
J6 "PEC02SAAN" CONN_PEC02SAAN 120,1368 r0 top
J10 "PEC02SAAN" CONN_PEC02SAAN 2507.73,1135.92 r90 top
J11 "PEC03SAAN" CONN_PEC03SAAN 1282.73,688.92 r180 top
J12 "PEC03SAAN" CONN_PEC03SAAN 1625.73,688.92 r180 top
J13 "PEC03SAAN" CONN_PEC03SAAN 1963.73,688.92 r180 top
J14 "PEC03SAAN" CONN_PEC03SAAN 2304.73,688.92 r180 top
J16 "1751248" CONN_1751248 138,2068.9 r270 top
J18 "1751248" CONN_1751248 146,3249.01 r270 top
J19 "1751248" CONN_1751248 3101.9,2887 r0 top
J20 "1751248" CONN_1751248 4780,3249 r90 top
J21 "1751248" CONN_1751248 3181.49,147.84 r0 top
L1 "NR3015T3R3M" NR3015 612.74,4492.1 r0 top value=3.3uH
L2 "744025006" WE-TPC_2828 992.74,4229.1 r270 top value=6.8uH
L3 "VLS2012ET-R47N" VLS2012ET 363,3720.26 r270 top value=470nH
L4 "NR3015T3R3M" NR3015 3924.71,4542.09 r0 top value=3.3uH
L5 "BLM41PG102SN1L" 1806_HighSpeed 3385,3891 r0 top value="1000 ohm"
L6 "NR3015T3R3M" NR3015 4238.38,3981.26 r270 top value=3.3uH
L7 "MPZ2012S601A" 0805_HV 2840.74,3421.24 r90 top value="600 ohm"
L8 "74456115" WE-PD4-L 4027,1489 r0 top value=15uH
L9 "744052005" WE-TPC-L 4741,818 r90 top value=5uH
L10 "7447730" WE-PD2-S 1358,134 r0 top value=1uH
L11 "74437324015" IND_WE-LHMI-4020 3332,399 r0 top value=1.5uH
L12 "VLCF4020T-2R2N1R7" VLCF4020 3030.49,946.84 r270 top value=2.2uH
L13 "VLCF4020T-2R2N1R7" VLCF4020 3371.49,1303.11 r0 top value=2.2uH
L14 "VLCF4020T-3R3N1R5" VLCF4020 3030.49,1155.84 r90 top value=3.3uH
L15 "74437324010" IND_WE-LHMI-4020 4511,4716 r0 top value=1uH
L16 "7447789002" WE-PD_7332_PlasticBase 2209,2945 r0 top value=2.2uH
L17 "MPZ2012S601A" 0805_HV 2838,3552 r0 top value="600 ohm"
L18 "XFL4015-471MEC" XFL4015 2768,2391 r270 top value=470nH
L19 "74438343022" WE-MAPI_2010 776.97,135.53 r180 top value=2.2uH
LBL1 "Size: 0.65\" x 0.20 \"" Label_650x200 4561,1775 r0 top
Logo2 "Pb-Free Symbol" Pb-Free_Overlay_Small 423,1608 r0 top
Logo3 "FCC disclaimer" FCC_disclaimer_stacked 3744.42,86.61 r0 top
Logo4 "ESD Susceptible" ESD_Overlay_Medium 167,1667 r0 top
NT1 "Net-Tie" Net-Tie_10mil 1984.67,4111.67 r0 top net-tie
Q1 "SI2323DS" SOT-23 3888,877 r90 top value=-20V
Q2 "SI2323DS" SOT-23 4527,767 r0 top value=-20V
Q3 "CSD18504Q5A" DQJ0008A 913.91,3127.04 r270 top value=40V
Q4 "CSD18504Q5A" DQJ0008A 3987,3229.43 r180 top value=40V
Q5 "CSD17571Q2" DQK0006C#1 907,3455.26 r0 top value=30V
Q6 "CSD17571Q2" DQK0006C#2 3668,1564 r0 top value=30V
R1 "CRCW060380K6FKEA" 0603L 2918.87,4449.77 r90 top value=80.6k
R2 "CRCW060340K2FKEA" 0603L 2891.07,4354.87 r0 top value=40.2k
R3 "CRCW060397K6FKEA" 0603L 1839.01,3497.77 r0 top value=97.6k
R4 "CRCW06038K87FKEA" 0603L 1866.01,4075.77 r270 top value=8.87k
R5 "RC0603FR-07240KL" 0603#1 2217.5,4453.99 r90 top value=240k
R6 "RC0603FR-0753K6L" 0603#1 2186.01,4356.99 r0 top value=53.6k
R7 "CRCW0402487KFKED" 0402#1 145,3694.26 r270 top value=487k
R8 "RC0402FR-071ML" 0402L 133,3770.26 r180 top value=1.00Meg
R9 "CRCW040222K6FKED" 0402#1 978.74,4668.1 r180 top value=22.6k
R10 "CRCW0402100KFKED" 0402#1 978.74,4717.1 r180 top value=100k
R11 "RC0603FR-07162KL" 0603L 95,3690.26 r90 top value=162k
R12 "ERJ-6ENF1003V" 0805_HV 1306,3837.26 r0 top value=100k
R13 "ERJ-6ENF1003V" 0805_HV 1306,3751.26 r0 top value=100k
R14 "ERJ-6ENF1003V" 0805_HV 1306,3654.26 r0 top value=100k
R15 "CRCW06031K00JNEA" 0603#1 944,3849.26 r180 top value=1.0k
R16 "CRCW06031K00JNEA" 0603#1 1080,3849.26 r180 top value=1.0k
R17 "CRCW0402100KFKED" 0402#1 816.74,4556.1 r180 top value=100k
R18 "RC0603FR-075K11L" 0603#1 1924.01,4079.77 r270 top value=5.11k
R19 "CRCW040210K0FKED" 0402#1 4015.33,3617.09 r0 top value=10.0k
R20 "RC0603FR-07100KL" 0603#1 2591,2078 r180 top value=100k
R21 "CRCW040210K0JNED" 0402#1 3224.12,4713.46 r180 top value=10k
R22 "CRCW040210K0FKED" 0402#1 3141.12,4399.46 r180 top value=10.0k
R23 "CRCW040210K0JNED" 0402#1 3329.12,4713.46 r0 top value=10k
R24 "CRCW040210K0FKED" 0402#1 3141.12,4449.46 r0 top value=10.0k
R25 "RC0603FR-0780K6L" 0603#1 2988,3784.5 r90 top value=80.6k
R26 "CRCW0402100KFKED" 0402#1 3267.74,3509 r180 top value=100k
R27 "CRCW060334K8FKEA" 0603#1 3125.74,3477 r90 top value=34.8k
R28 "CRCW040259K0FKED" 0402#1 3181.74,3485 r90 top value=59.0k
R29 "ERJ-3EKF4993V" 0603#1 2761,3809.5 r90 top value=499k
R30 "RC0603FR-07162KL" 0603#1 2983,3663 r0 top value=162k
R31 "CRCW040211K3FKED" 0402#1 3267.74,3459 r180 top value=11.3k
R32 "RC0603FR-07110KL" 0603#1 4027.71,3560.09 r0 top value=110k
R33 "CRCW060344K2FKEA" 0603#1 4027.71,3497.09 r180 top value=44.2k
R34 "CRCW060344K2FKEA" 0603#1 3993.71,3788.09 r90 top value=44.2k
R35 "RC0603FR-07200KL" 0603#1 2605.74,3572.24 r180 top value=200k
R36 "ERJ-3EKF4993V" 0603#1 2567,3345 r0 top value=499k
R37 "RC0603FR-07162KL" 0603#1 2669,3637 r180 top value=162k
R38 "RC0603FR-07100KL" 0603#1 2591,1860 r180 top value=100k
R39 "CRCW0402118KFKED" 0402#1 4807.4,3530.2 r270 top value=118k
R40 "CRCW0402150KFKED" 0402#1 4857,3530.38 r90 top value=150k
R41 "CRCW06031M00FKEA" 0603#1 340,1176 r270 top value=1.00Meg
R42 "CRCW0603487RFKEA" 0603#1 612,1220 r270 top value=487
R43 "RC0603FR-071K02L" 0603#1 677,1220 r270 top value=1.02k
R44 "CRCW06034K42FKEA" 0603#1 742,1220 r270 top value=4.42k
R45 "RC0603FR-07240KL" 0603#1 1745.73,1213.92 r180 top value=240k
R46 "RC0603FR-07470KL" 0603#1 1505.73,1426.92 r0 top value=470k
R47 "RC0603FR-07470KL" 0603#1 1376.73,1426.99 r180 top value=470k
R48 "CRCW0603205KFKEA" 0603#1 1745.73,1151.92 r0 top value=205k
R49 "RC0603FR-07120KL" 0603#1 1746,1087 r0 top value=120k
R50 "RC0603FR-07470KL" 0603#1 1505.73,1364.92 r180 top value=470k
R51 "RC0603FR-07470KL" 0603#1 1376.73,1364.86 r0 top value=470k
R52 "RC0603FR-071KL" 0603#1 2307.73,790.92 r180 top value=1.00k
R53 "RC0603FR-071KL" 0603#1 2435.73,790.92 r180 top value=1.00k
R54 "CRCW0402100KFKED" 0402#1 1254.1,1718.51 r180 top value=100k
R55 "ERJ-3GEY0R00V" 0603#1 1472.72,1811.51 r270 top value=0
R56 "RC0603FR-07100KL" 0603#1 939,1594 r0 top value=100k
R57 "RC0603FR-07100KL" 0603#1 1376.72,1843.51 r0 top value=100k
R58 "CRCW06032K87FKEA" 0603#1 1376.72,1781.51 r0 top value=2.87k
R59 "CRCW06031K15FKEA" 0603#1 1376.72,1719.51 r0 top value=1.15k
R60 "CRCW0603681RFKEA" 0603#1 1376.72,1657.51 r0 top value=681
R61 "CRCW0603464RFKEA" 0603#1 1376.72,1595.51 r0 top value=464
R62 "CRCW0603113KFKEA" 0603#1 1630.72,1759.51 r180 top value=113k
R63 "CRCW0603174KFKEA" 0603#1 1630.72,1822.51 r180 top value=174k
R64 "CRCW0603348KFKEA" 0603#1 1630.72,1885.51 r180 top value=348k
R65 "CRCW0603715KFKEA" 0603#1 1630.72,1948.51 r180 top value=715k
R66 "CRCW06031M21FKEA" 0603#1 1630.72,2011.51 r180 top value=1.21Meg
R67 "RC0603FR-07100KL" 0603#1 1630.72,2074.05 r180 top value=100k
R68 "CRCW0402360KFKED" 0402#1 1600,153 r90 top value=360k
R69 "CRCW0402182KFKED" 0402#1 1514,153 r90 top value=182k
R70 "ERJ-8CWFR033V" 1206 4014,772 r90 top value=0.033
R71 "ERJ-3GEY0R00V" 0603#1 4122,827 r270 top value=0
R72 "ERJ-3GEY0R00V" 0603#1 4003,348 r0 top value=0
R73 "ERJ-3GEY0R00V" 0603#1 4003,478 r0 top value=0
R74 "RC0603FR-07100KL" 0603#1 4003,412 r0 top value=100k
R75 "ERJ-3GEY0R00V" 0603#1 4373,348 r0 top value=0
R76 "ERJ-8CWFR033V" 1206 4383,777 r90 top value=0.033
R77 "CRCW04020000Z0ED" 0402#1 2882.49,821.84 r180 top value=0
R78 "CRCW0402165KFKED" 0402#1 3057.49,821.84 r180 top value=165k
R79 "CRCW0402200KFKED" 0402#1 3144.49,798.6 r90 top value=200k
R80 "CRCW06032R00JNEA" 0603#1 3212,1317 r270 bottom value=2.0
R81 "CRCW04020000Z0ED" 0402#1 3493.49,1455.11 r90 top value=0
R82 "CRCW0402301KFKED" 0402#1 3513.49,1279.11 r90 top value=301k
R83 "CRCW04020000Z0ED" 0402#1 2891.53,351 r270 top value=0
R84 "CRCW04020000Z0ED" 0402#1 2720.21,150 r0 top value=0
R85 "CRCW04024K99FKED" 0402#1 2720.21,201 r0 top value=4.99k
R86 "CRCW0402200KFKED" 0402#1 3537.62,1198.62 r180 top value=200k
R87 "CRCW04022K00FKED" 0402#1 2910,635.98 r270 top value=2.00k
R88 "CRCW04021K00FKED" 0402#1 2794,635.98 r90 top value=1.00k
R89 "CRCW04020000Z0ED" 0402#1 2877,1296 r180 top value=0
R90 "CRCW0402432KFKED" 0402#1 3054,1296 r180 top value=432k
R91 "CRCW04022K00FKED" 0402#1 2678.58,635.98 r90 top value=2.00k
R92 "CRCW040295K3FKED" 0402#1 3132,1320 r270 top value=95.3k
R93 "CRCW04020000Z0ED" 0402#1 3418,1182 r270 bottom value=0
R94 "CRCW04020000Z0ED" 0402#1 3420.49,868 r0 bottom value=0
R95 "CRCW04021K00FKED" 0402#1 2562,635.98 r90 top value=1.00k
R96 "CRCW0402162KFKED" 0402#2 3303.49,950.84 r0 bottom value=162k
R97 "CRCW0402200KFKED" 0402#1 3194.49,950.84 r0 bottom value=200k
R98 "CRCW04020000Z0ED" 0402#1 3420.49,819.84 r0 bottom value=0
R99 "CRCW0402162KFKED" 0402#1 3295.49,881.84 r0 bottom value=162k
R100 "CRCW0402200KFKED" 0402#1 3272.49,800.84 r90 bottom value=200k
R101 "CRCW0402100KJNED" 0402#1 3514.49,1058.84 r0 top value=100k
R102 "CRCW04020000Z0ED" 0402#1 3514.49,1009.84 r0 top value=0
R103 "RC0603FR-07100KL" 0603#1 4373,285 r0 top value=100k
R104 "ERJ-3GEY0R00V" 0603#1 4472,471 r270 top value=0
R105 "ERJ-3GEY0R00V" 0603#1 4409,471 r90 top value=0
R106 "RC0603FR-07100KL" 0603#1 4536,471 r270 top value=100k
R107 "CRCW060361K9FKEA" 0603#1 4235,796 r0 top value=61.9k
R108 "CRCW060336K5FKEA" 0603#1 4235,921 r180 top value=36.5k
R109 "CRCW060361K9FKEA" 0603#1 4233,445 r270 top value=61.9k
R110 "CRCW060310K0FKEA" 0603#1 1153,3030 r0 top value=10.0k
R111 "CRCW060315K4FKEA" 0603#1 4296,445 r90 top value=15.4k
R112 "ERJ-3EKF2202V" 0603#1 644,3894 r0 top value=22.0k
R113 "CRCW0402100KJNED" 0402#1 1401,435 r180 top value=100k
R114 "RG1608P-473-B-T5" 0603#1 749,3730.26 r270 top value=47.0k
R115 "CRCW060310K0FKEA" 0603#1 3863,2999.43 r270 top value=10.0k
R116 "RG1608P-473-B-T5" 0603#1 643,3832.26 r180 top value=47.0k
R117 "RG1608P-473-B-T5" 0603#1 686,3730.26 r270 top value=47.0k
R118 "ERJ-6RSJR10V" 0805_HV 469,3733.26 r270 top value=0.1
R119 "CRCW060337K4FKEA" 0603#1 569.81,707.48 r0 top value=37.4k
R120 "ERJ-3EKF1001V" 0603#1 425,734 r0 top value=1.00k
R121 "CRCW060310K0FKEA" 0603#1 572,644 r180 top value=10.0k
R122 "RG1608P-104-B-T5" 0603#1 4155.74,4714 r90 top value=100k
R123 "RC0603FR-0719K1L" 0603#1 4218,4714 r270 top value=19.1k
R124 "RC0603FR-0724K3L" 0603#1 4155.74,4583 r90 top value=24.3k
R125 "RT0603BRD0764K2L" 0603#1 3108.3,2347.31 r180 top value=64.2k
R126 "ERJ-3EKF1002V" 0603#1 3204.37,2317.31 r90 top value=10.0k
R127 "RG1608P-104-B-T5" 0603#1 3621.3,2379.31 r180 top value=100k
R128 "CRCW060328K7FKEA" 0603#1 3108.3,2415.31 r180 top value=28.7k
R129 "ERJ-3EKF1002V" 0603#1 3204.3,2447.31 r270 top value=10.0k
R130 "RC0603FR-0747KL" 0603#1 3333.3,2579.31 r90 top value=47.0k
R131 "ERJ-3EKF1002V" 0603#1 3236.3,2548.31 r0 top value=10.0k
R132 "CRCW06032K00JNEA" 0603#1 2549.54,3908.41 r90 top value=2.0k
R133 "CRCW06032K00JNEA" 0603#1 2675.54,3906.41 r90 top value=2.0k
R134 "CRCW06032K00JNEA" 0603#1 1410,496 r0 top value=2.0k
R135 "CRCW0603300RJNEA" 0603#1 1194,3466.26 r0 top value=300
R136 "CRCW0603300RJNEA" 0603#1 774,3430.26 r180 top value=300
R137 "RMCF0603ZT0R00" 0603#1 623,3600.26 r270 top value=0
R138 "RG1608P-473-B-T5" 0603#1 686,3600.26 r90 top value=47.0k
R139 "RC0603FR-0747KL" 0603#1 2718,4356 r180 top value=47.0k
R140 "CRCW06032K00JNEA" 0603#1 3000,4112.72 r0 top value=2.0k
R141 "RC0603FR-0747KL" 0603#1 2003.5,4357.06 r180 top value=47.0k
R142 "CRCW06032K00JNEA" 0603#1 3000,4248.91 r0 top value=2.0k
R143 "ERJ-3GEY0R00V" 0603#1 2071.23,2365.47 r90 top value=0
R144 "ERJ-3GEY0R00V" 0603#1 1938.23,2148.47 r0 top value=0
R145 "ERJ-3GEY0R00V" 0603#1 2071.23,2200.47 r90 top value=0
R146 "CR0603-JW-472GLF" 0603#1 4102,2026 r180 top value=4.7k
R147 "CR0603-JW-472GLF" 0603#1 4102,2095 r180 top value=4.7k
R148 "CR0603-JW-472GLF" 0603#1 4102,2285 r180 top value=4.7k
R149 "CR0603-JW-472GLF" 0603#1 4584,2120 r0 top value=4.7k
R150 "CR0603-JW-472GLF" 0603#1 4584,2031 r0 top value=4.7k
R151 "CRCW06030000Z0EA" 0603#1 4102,1961 r180 top value=0
R152 "CRCW06030000Z0EA" 0603#1 4102,2158 r180 top value=0
R153 "CRCW06030000Z0EA" 0603#1 4102,2221 r180 top value=0
R154 "ERJ-3GEY0R00V" 0603#1 2084,3253 r180 top value=0
R155 "ERJ-3EKF1002V" 0603#1 1587,3187 r0 top value=10.0k
R156 "RC0603FR-0713K7L" 0603#1 1717,3187 r0 top value=13.7k
R157 "ERA-3ARW104V" 0603#1 1587,2948 r0 top value=100k
R158 "ERA-3ARW104V" 0603#1 1780,2822 r0 top value=100k
R159 "ERJ-3GEY0R00V" 0603#1 1780,2887 r180 top value=0
R160 "CRCW040210K0FKED" 0402M 3625,1796 r0 top value=10.0k
R161 "CRCW06030000Z0EA" 0603#1 3804,1864 r0 top value=0
R162 "CRCW040210K0FKED" 0402M 3491,1875 r270 top value=10.0k
R163 "CRCW040210K0FKED" 0402M 3491,2012 r90 top value=10.0k
R164 "CRCW040210K0FKED" 0402M 3183,1914 r180 top value=10.0k
R165 "CRCW06030000Z0EA" 0603#1 3305.01,2048 r0 top value=0
R166 "CRCW08050000Z0EA" 0805_HV 4235.58,4257.39 r180 top value=0
R167 "CRCW08050000Z0EA" 0805_HV 4235.58,4121.39 r180 top value=0
R168 "RC0603FR-0730K9L" 0603#1 4840,4104 r180 top value=30.9k
R169 "ERJ-3EKF1002V" 0603#1 4840,4180 r180 top value=10.0k
R170 "CRCW08050000Z0EA" 0805_HV 3079,3588 r0 top value=0
R171 "ERJ-6GEY0R00V" 0805_HV 2585,2562 r0 top value=0
R172 "ERA-3AEB104V" 0603#1 2392.5,2459.5 r0 bottom value=100k
R173 "ERA-3AEB104V" 0603#1 2712,2547 r270 top value=100k
R174 "ERA-3AEB104V" 0603#1 2361,2428 r270 top value=100k
R175 "ERA-3AEB104V" 0603#1 2424,2428 r90 top value=100k
R176 "CRCW08050000Z0EA" 0805_HV 783,4071 r0 top value=0
R177 "CRCW08050000Z0EA" 0805_HV 2305,3727 r180 top value=0
R178 "CRCW04023K30JNED" 0402L 3496,461 r90 top value=3.3k
R179 "CRCW08050000Z0EA" 0805_HV 1206,1377 r270 top value=0
R180 "CRCW08050000Z0EA" 0805_HV 700,1611 r270 top value=0
R181 "CRCW08050000Z0EA" 0805_HV 1023,534 r270 top value=0
R182 "CRCW08050000Z0EA" 0805_HV 830,537 r90 top value=0
R183 "RT0603DRE07976RL" 0603#1 865.97,288.53 r90 top value=47.5k
R184 "RT0603DRE07976RL" 0603#1 596.97,387.53 r180 top value=536k
R185 "RT0603DRE07976RL" 0603#1 596.97,321.53 r0 top value=120k
R186 "CRCW060310R0FKEAHP" 0603#1 4308,2464 r270 top value=10.0
R187 "CRCW08050000Z0EA" 0805_HV 1863,4329 r0 bottom value=0
R188 "CRCW0603300RJNEA" 0603#1 3810,1702 r90 top value=300
R189 "CRCW0603300RJNEA" 0603#1 3662,1466 r0 top value=300
R190 "RMCF0603ZT0R00" 0603#1 3668,1202.5 r90 top value=0
RB1 "CRCW040230R1FKED" 0402#1 841.74,4695.1 r90 top value=30.1
RES1 "RG1608P-104-B-T5" 0603#1 1068.74,4708.1 r270 top value=100k
S1 "B3U-1100P" SW_B3U-1100P 3398.3,2260.31 r180 top
TP1 "" Keystone5000 649,4650 r0 top
TP2 "" Keystone5000 2151.01,3714.77 r0 top
TP3 "" Keystone5000 463,3550 r180 top
TP4 "5001" Keystone5001 2151.01,4022.77 r0 top
TP5 "" Keystone5000 1802.36,4544.56 r90 top
TP6 "" Keystone5000 2917.07,4806.57 r90 top
TP7 "5001" Keystone5001 2758.07,4806.57 r0 top
TP8 "" Keystone5000 2200.5,4806.56 r0 top
TP9 "5001" Keystone5001 2048.5,4806.56 r0 top
TP10 "" Keystone5000 3114.12,4805.46 r180 top
TP11 "" Keystone5000 3384.86,4806.46 r180 top
TP12 "5000" Keystone5000 2984,3480 r90 top
TP13 "5000" Keystone5000 2988,4005.5 r0 top
TP14 "" Keystone5000 3959.71,4021 r0 top
TP15 "" Keystone5000 3432,4053 r180 top
TP16 "" Keystone5000 3611,3399 r90 top
TP17 "5001" Keystone5001 2842,4005.5 r0 top
TP18 "" Keystone5000 2984,3343 r0 top
TP19 "" Keystone5000 2361.35,3570.24 r90 top
TP20 "" Keystone5000 4783,3990 r90 top
TP21 "5001" Keystone5001 2361.35,3416.24 r90 top
TP22 "5000" Keystone5000 569,823 r90 top
TP23 "5000" Keystone5000 902,1059 r180 top
TP24 "5003" Keystone5003 296,1370 r180 top
TP25 "5003" Keystone5003 902,1209 r90 top
TP26 "5003" Keystone5003 440,1370 r180 top
TP27 "5003" Keystone5003 902,1350 r90 top
TP28 "5000" Keystone5000 482,1763 r180 top
TP29 "5000" Keystone5000 426,2458 r270 top
TP30 "5003" Keystone5003 1236.72,1595.51 r180 top
TP31 "5003" Keystone5003 1646.72,2256.51 r270 top
TP32 "5003" Keystone5003 1507.72,1595.51 r270 top
TP33 "5003" Keystone5003 1638.72,1595.51 r270 top
TP34 "5003" Keystone5003 1067.72,1595.51 r180 top
TP35 "" Keystone5000 999.74,4089.1 r90 top
TP36 "5000" Keystone5000 4392,1490 r0 top value=Red
TP37 "5001" Keystone5001 4558,1490 r0 top value=Black
TP38 "5000" Keystone5000 4766,1297 r0 top value=Red
TP39 "5001" Keystone5001 4558,1297 r0 top value=Black
TP40 "5000" Keystone5000 4268,202 r0 top value=Red
TP41 "5000" Keystone5000 1260,2842 r0 top value=Red
TP42 "5001" Keystone5001 4118,202 r90 top value=Black
TP43 "5001" Keystone5001 896,2842 r0 top value=Black
TP44 "5001" Keystone5001 3329,1596.11 r180 top
TP45 "5001" Keystone5001 2749.49,1049.39 r180 top
TP46 "5001" Keystone5001 3097,571 r180 top
TP47 "5002" Keystone5002 1173.74,4720.1 r90 top
TP48 "5002" Keystone5002 1893,4221 r0 top
TP49 "5002" Keystone5002 2755,4114 r0 top
TP50 "5002" Keystone5002 2029,4221 r180 top
TP51 "5002" Keystone5002 4095.71,3714.09 r90 top
TP52 "" Keystone5000 2077.73,1367.92 r0 top
TP53 "5001" Keystone5001 1888.73,1125.92 r270 top
TP54 "5003" Keystone5003 2498,2174 r180 top
TP55 "5000" Keystone5000 1773,142 r90 top value=Red
TP56 "5001" Keystone5001 1761,473 r180 top value=Black
TP57 "" Keystone5000 2744,2043 r90 top
TP58 "5001" Keystone5001 2744,1905 r90 top
TP59 "5001" Keystone5001 953,2095.51 r180 top
TP60 "" Keystone5000 2744,1755 r180 top
TP61 "5001" Keystone5001 2449,1572 r180 top
TP62 "5002" Keystone5002 4238,3805 r90 top
TP63 "5002" Keystone5002 96.81,823 r0 top
TP64 "5002" Keystone5002 96.81,534.48 r0 top
TP65 "5002" Keystone5002 347,358 r270 top
TP66 "5002" Keystone5002 96.81,681.48 r270 top
TP67 "5002" Keystone5002 96.81,399.48 r270 top
TP68 "" Keystone5000 4696,4531 r90 top
TP69 "5001" Keystone5001 4591,4338 r0 top
TP70 "5003" Keystone5003 3819,2391 r180 top
TP71 "5000" Keystone5000 1256,518 r90 top
TP72 "5002" Keystone5002 1324,3948.26 r90 top
TP73 "5002" Keystone5002 1131,3948.26 r90 top
TP74 "5002" Keystone5002 1324,3519 r90 top
TP75 "" Keystone5000 806,3948.26 r90 top
TP76 "" Keystone5000 3252.12,4806.46 r180 top
TP77 "" Keystone5000 4635,3843.82 r180 top
TP78 "5001" Keystone5001 4783,3843.82 r90 top
TP79 "5003" Keystone5003 3819,2053 r270 top
TP80 "" Keystone5000 3432,4237 r180 top
TP81 "" Keystone5000 2749.49,821.84 r180 top
TP82 "" Keystone5000 3493.49,1596.11 r180 top
TP83 "" Keystone5000 2749.49,1297 r270 top
TP84 "" Keystone5000 3550.49,915.84 r180 top
TP85 "" Keystone5000 3550,725 r180 top
TP86 "5001" Keystone5001 902,889 r90 top
TP87 "5000" Keystone5000 3720,845 r0 top
TP88 "5002" Keystone5002 4746,2075 r180 top
TP89 "5002" Keystone5002 4746,2228 r180 top
TP90 "5002" Keystone5002 4565,2228 r180 top
TP91 "5000" Keystone5000 2438,3054 r90 top value=Red
TP92 "5002" Keystone5002 1492,2842 r90 top
TP93 "5001" Keystone5001 1949,2857 r90 top value=Black
TP94 "5002" Keystone5002 1631,2842 r90 top
TP95 "5000" Keystone5000 3719,3269.53 r90 top value=Red
TP96 "5001" Keystone5001 3719,2942.53 r90 top value=Black
TP97 "5003" Keystone5003 3667.39,1059.42 r90 top
TP98 "5002" Keystone5002 526,3972 r90 top
TP99 "" Keystone5000 2448,4023 r90 top
TP100 "5002" Keystone5002 2349,3911 r90 top
TP101 "5001" Keystone5001 2171,4221 r90 top
TP102 "" Keystone5000 2707,4260 r90 top
TP103 "5003" Keystone5003 2182,2327 r90 top
TP104 "" Keystone5000 2744,2220 r180 top
TP105 "5003" Keystone5003 2818,2547 r90 top
TP106 "5001" Keystone5001 2342,2273 r90 top
TP107 "" Keystone5000 4451,3493 r90 top
TP108 "" Keystone5000 2140,2522 r90 top
TP109 "5000" Keystone5000 395,136 r90 top value=Red
TP110 "5002" Keystone5002 4470,2433 r90 top
TP111 "" Keystone5000 2993,422 r0 top
U1 "LMZ34202RVQ" RVQ0043A 1772.01,3762.67 r90 top
U2 "LMZ20502SILR" SIL0008F 2808.01,4479.5 r90 top
U3 "LMZ20501SILR" SIL0008F 2093.75,4479.93 r90 top
U4 "LM53635AQRNLTQ1" RNL0022A_NV 991.74,4507.1 r0 top
U5 "TPS62085RLTR" RLT0007A 243,3746.26 r0 top
U6 "TVS3300DRVR" DRV0006A 355.41,4372.39 r90 top
U7 "LP2998MRX/NOPB" DDA0008A_L 2433,4517.35 r90 top
U8 "LM3881MM/NOPB" MUA08A_N 1079,3737.26 r0 top
U9 "TVS3300DRVR" DRV0006A 1644.05,4556.26 r0 top
U10 "TPS62821DLCR" DLC0008A 2511,2448 r0 top
U11 "TPS51200DRCR" DRC0010J 3275.12,4591.46 r90 top
U12 "LMZM33602RLR" RLR0018A 3743.71,3632.09 r270 top
U13 "TPS82130SILR" SIL0008D_SMD 3230.74,3617 r270 top
U14 "TPS82084SILR" SIL0008C_SMD 2875.69,3765.12 r0 top
U15 "TVS3300DRVR" DRV0006A 3741.71,4542.09 r0 top
U16 "TLV62565DBVR" DBV0005A_N 759.97,270.53 r90 top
